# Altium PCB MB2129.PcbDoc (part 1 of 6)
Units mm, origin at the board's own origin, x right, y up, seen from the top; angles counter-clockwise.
Board outline 70 x 133.34 mm, 6 copper layers (Top Layer, Signal Layer 1, Signal Layer 2, Signal Layer 3, Signal Layer 4, Bottom Layer), stack 1.57 mm thick; 377 components, 289 nets, 1482 pads, 1373 vias.
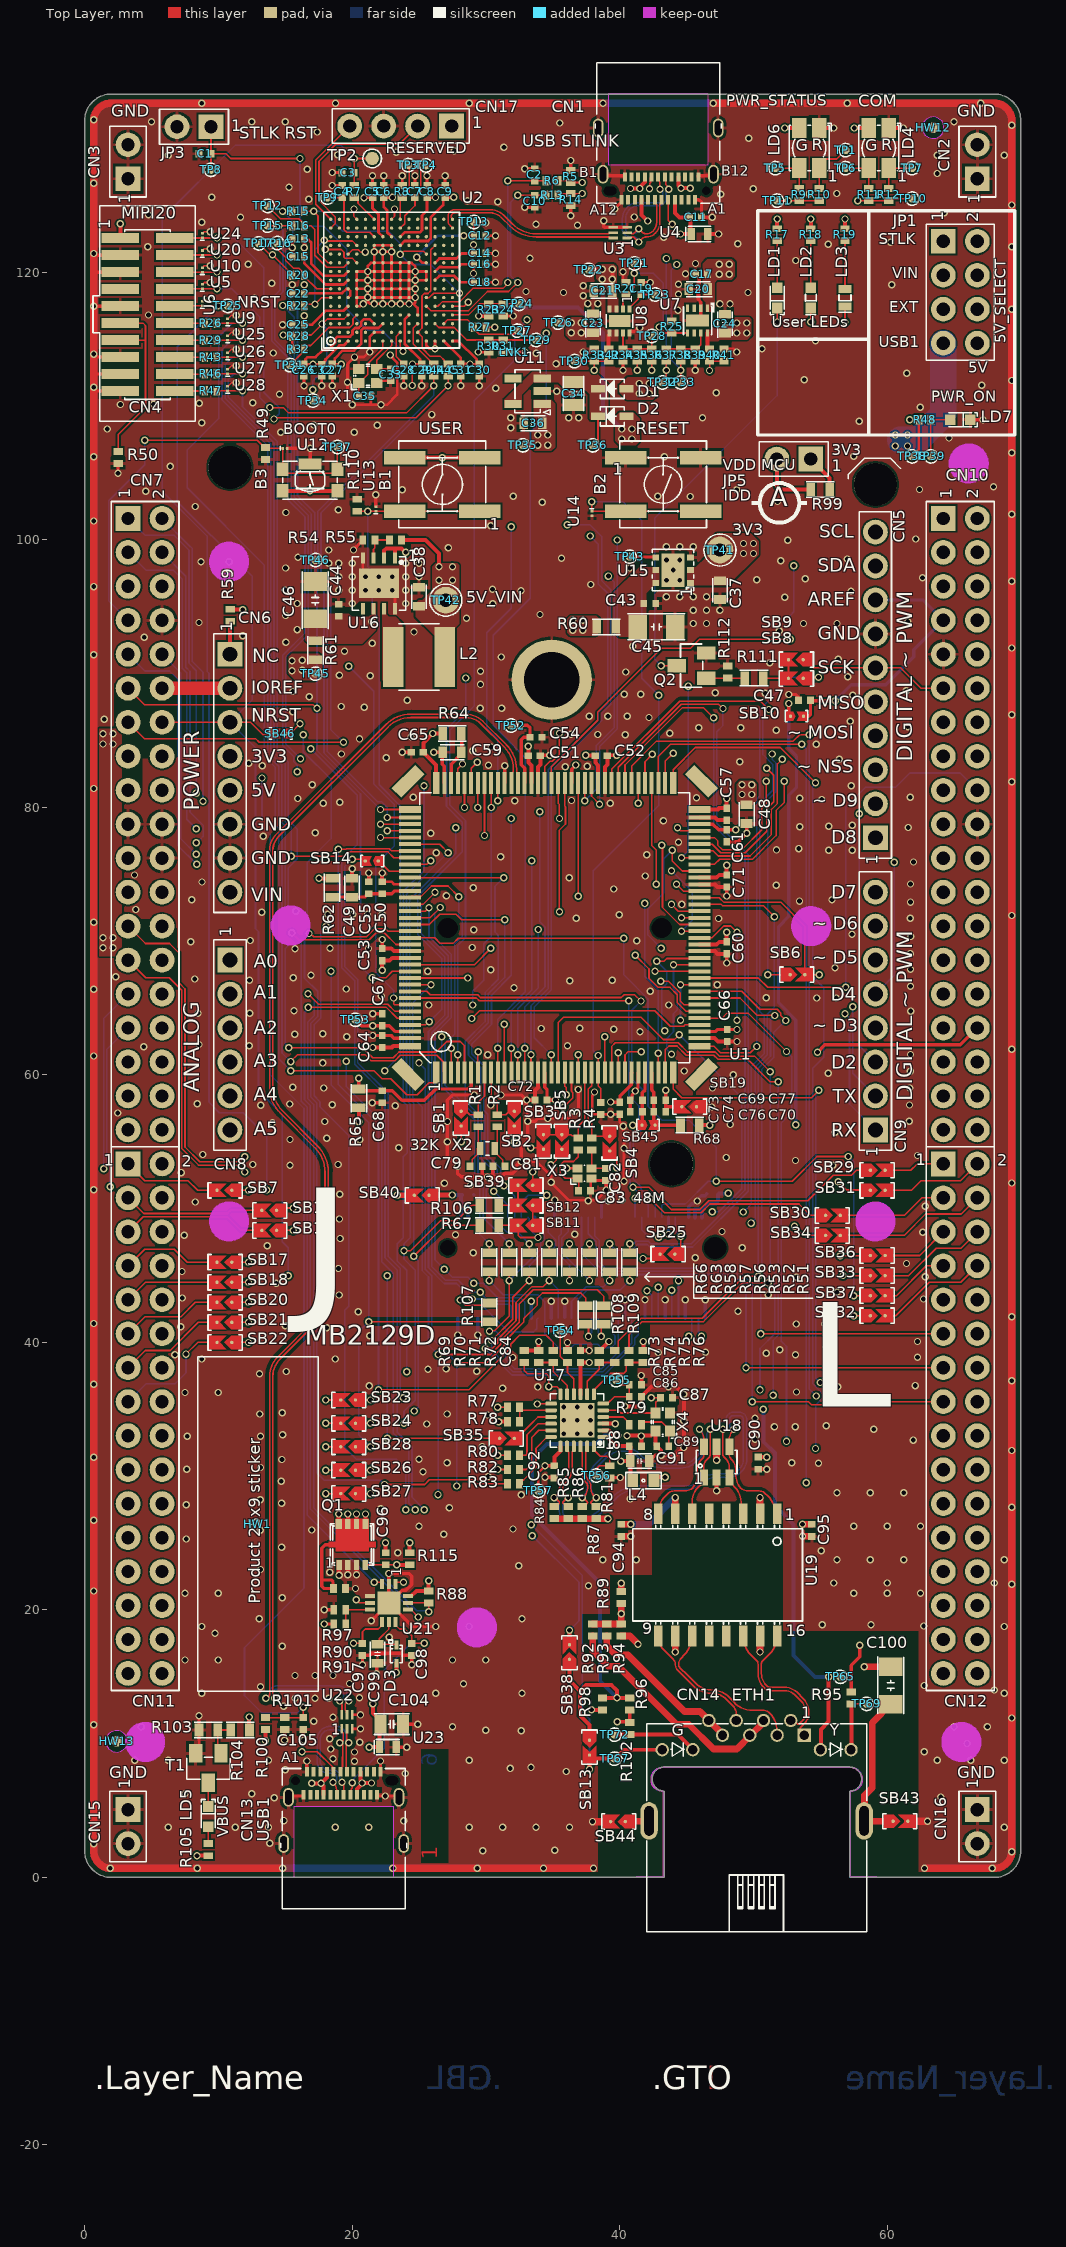
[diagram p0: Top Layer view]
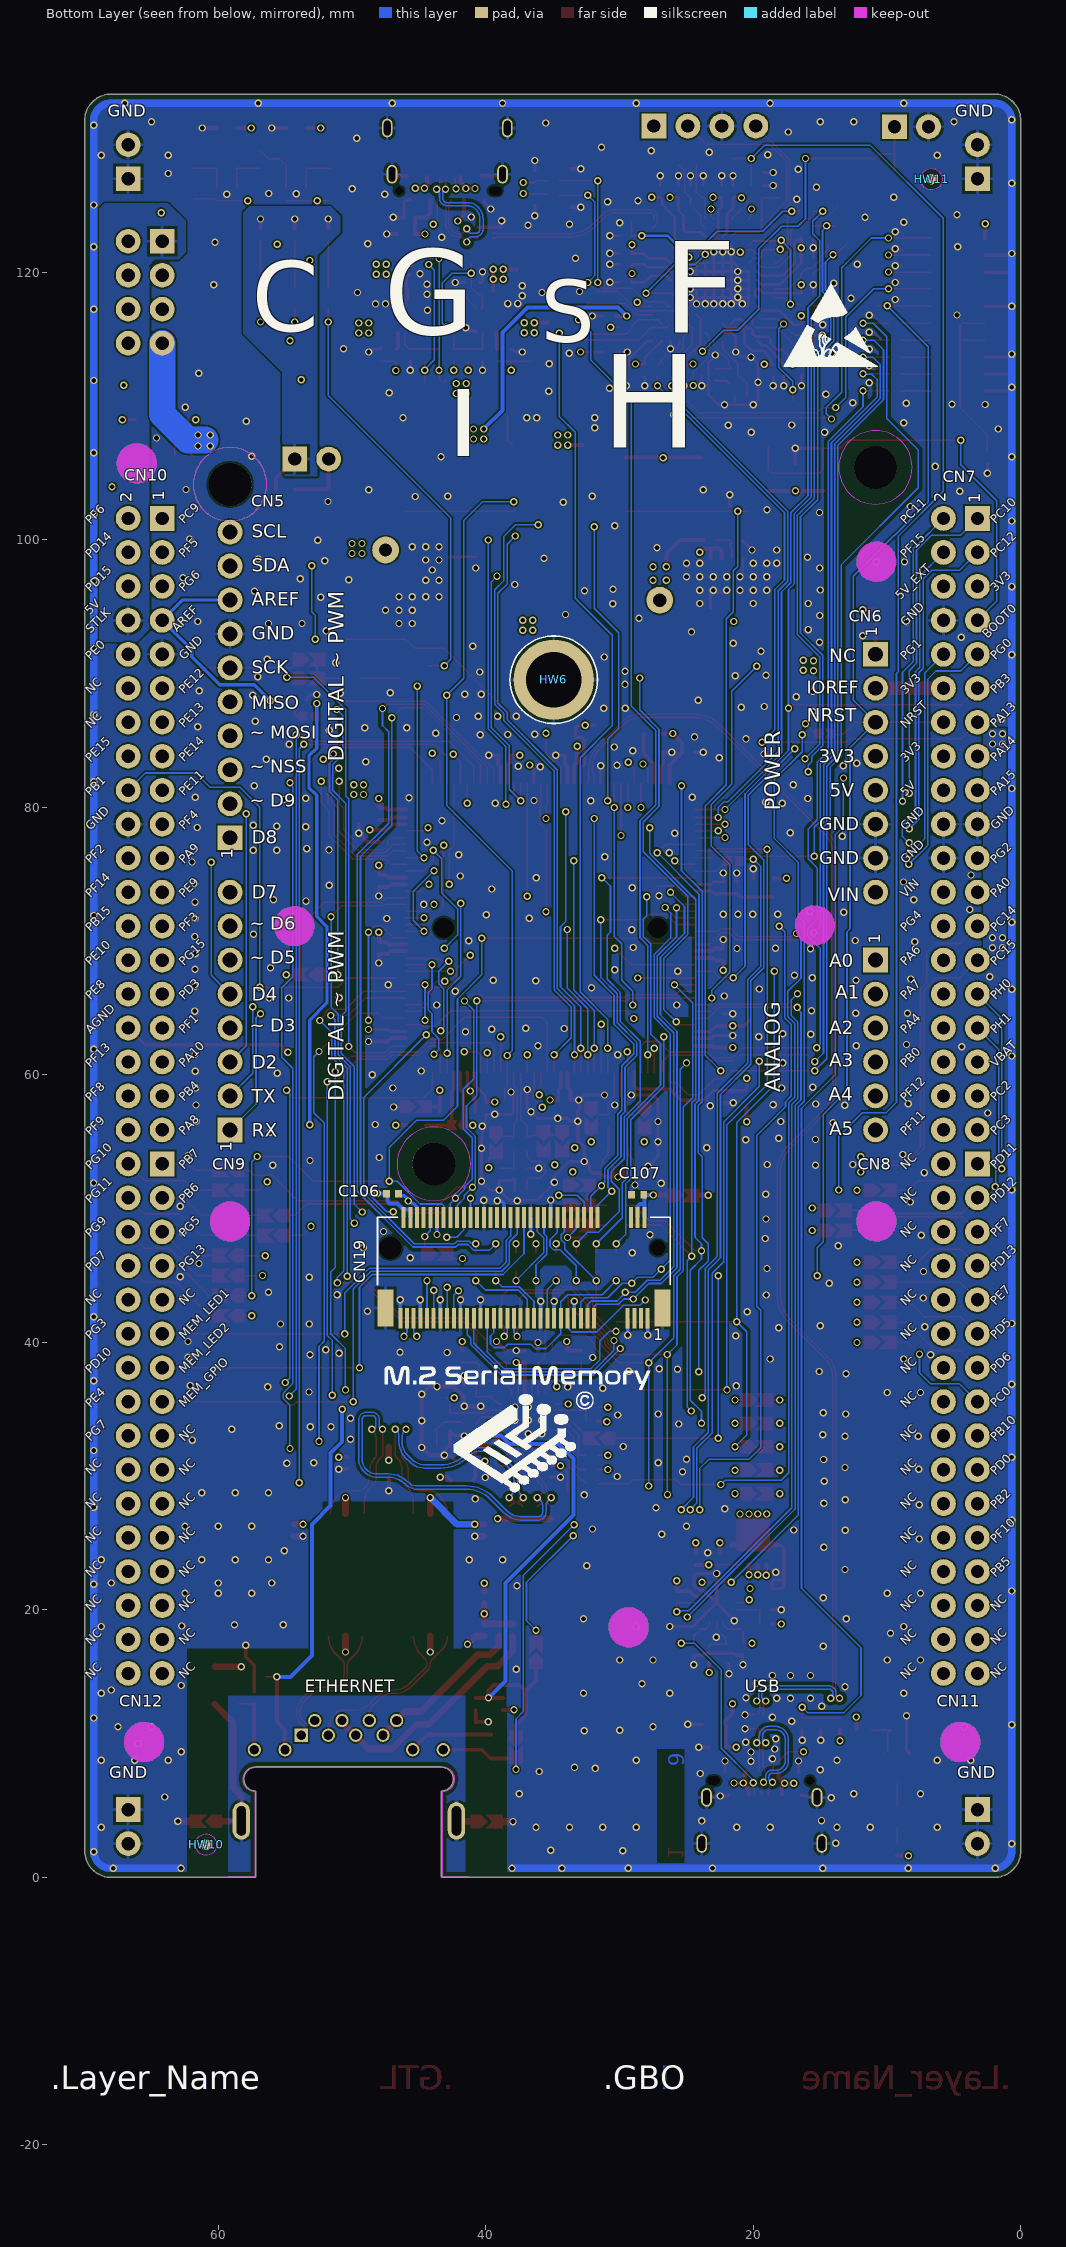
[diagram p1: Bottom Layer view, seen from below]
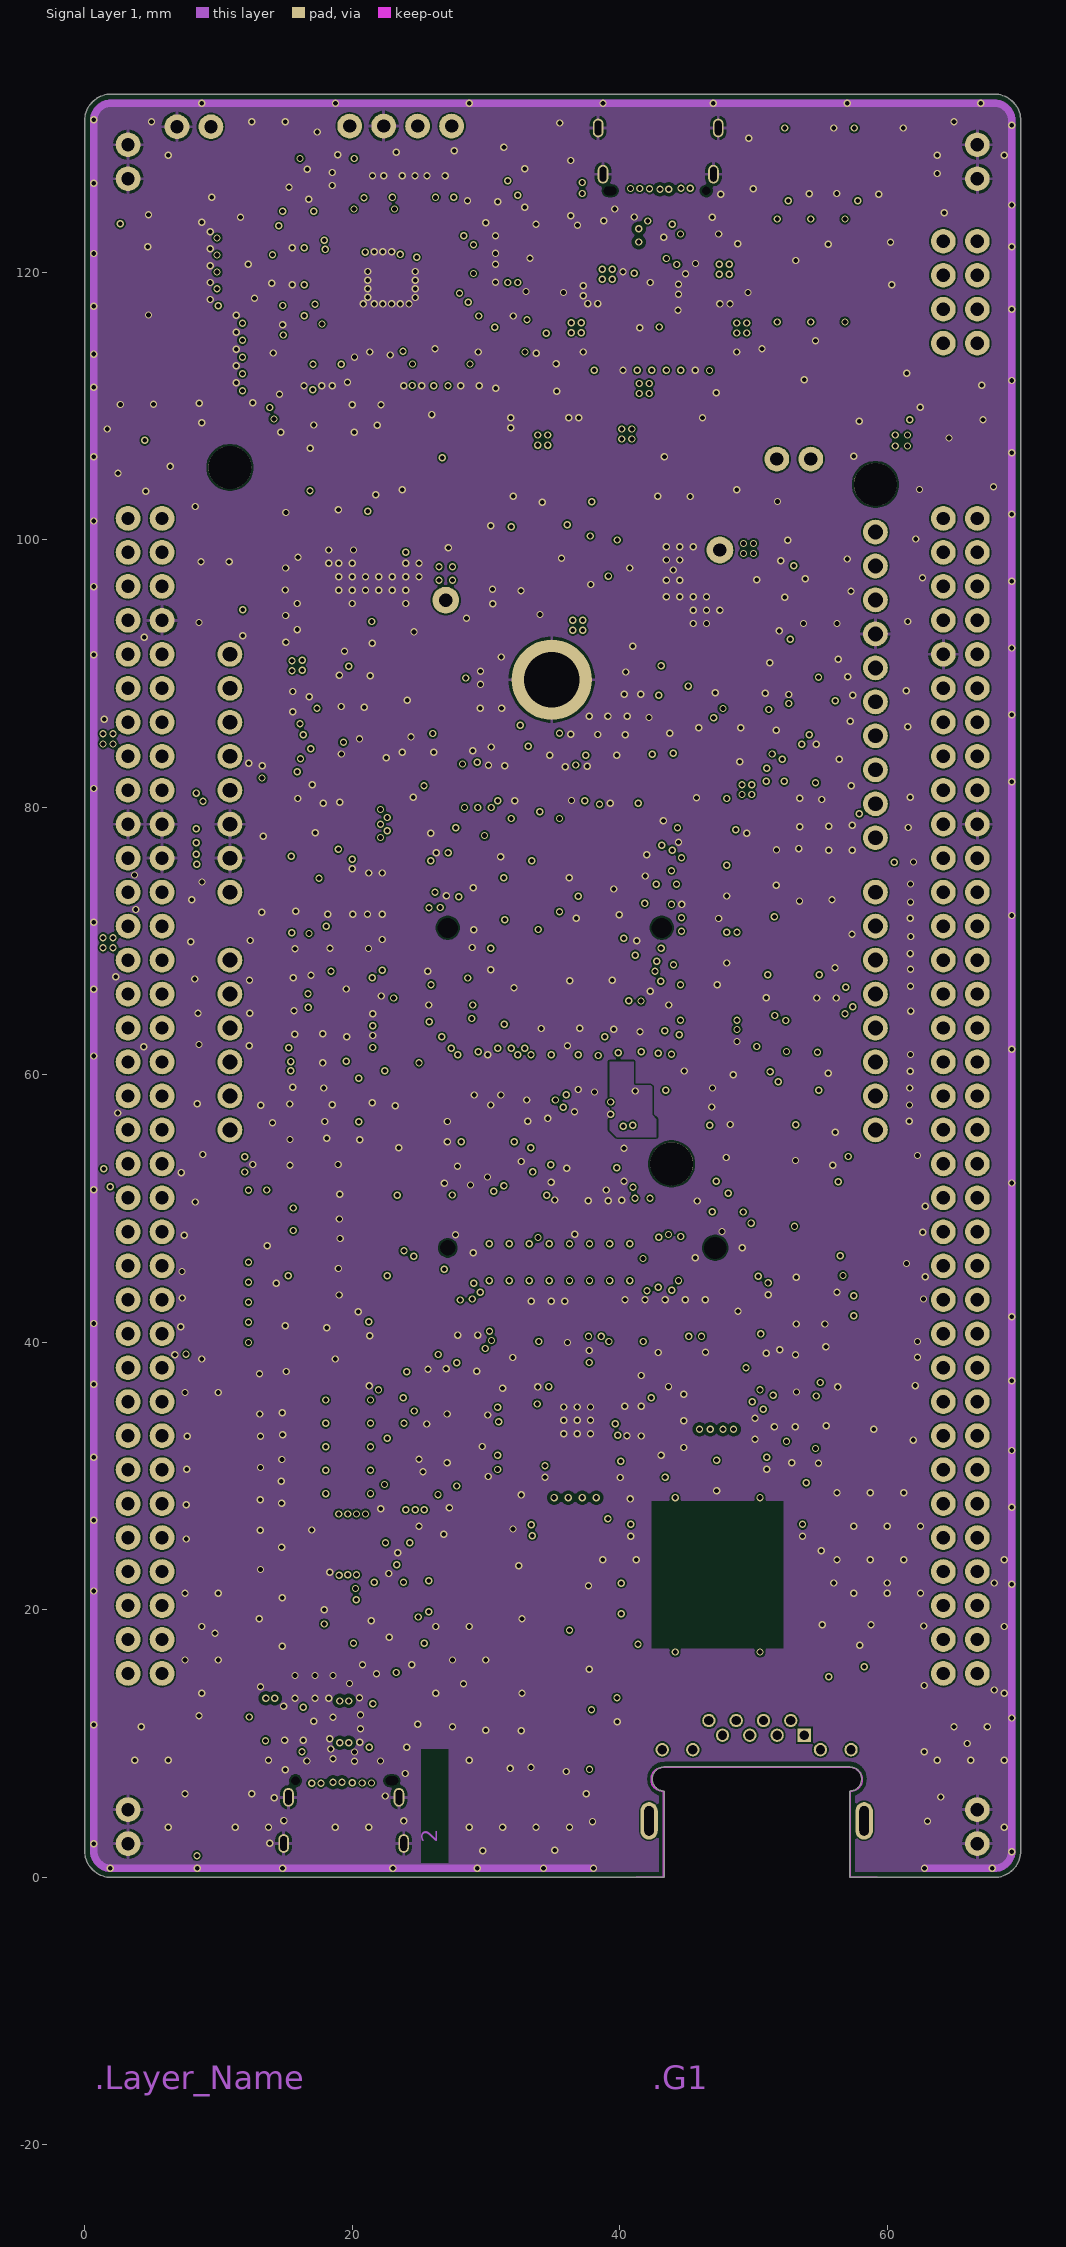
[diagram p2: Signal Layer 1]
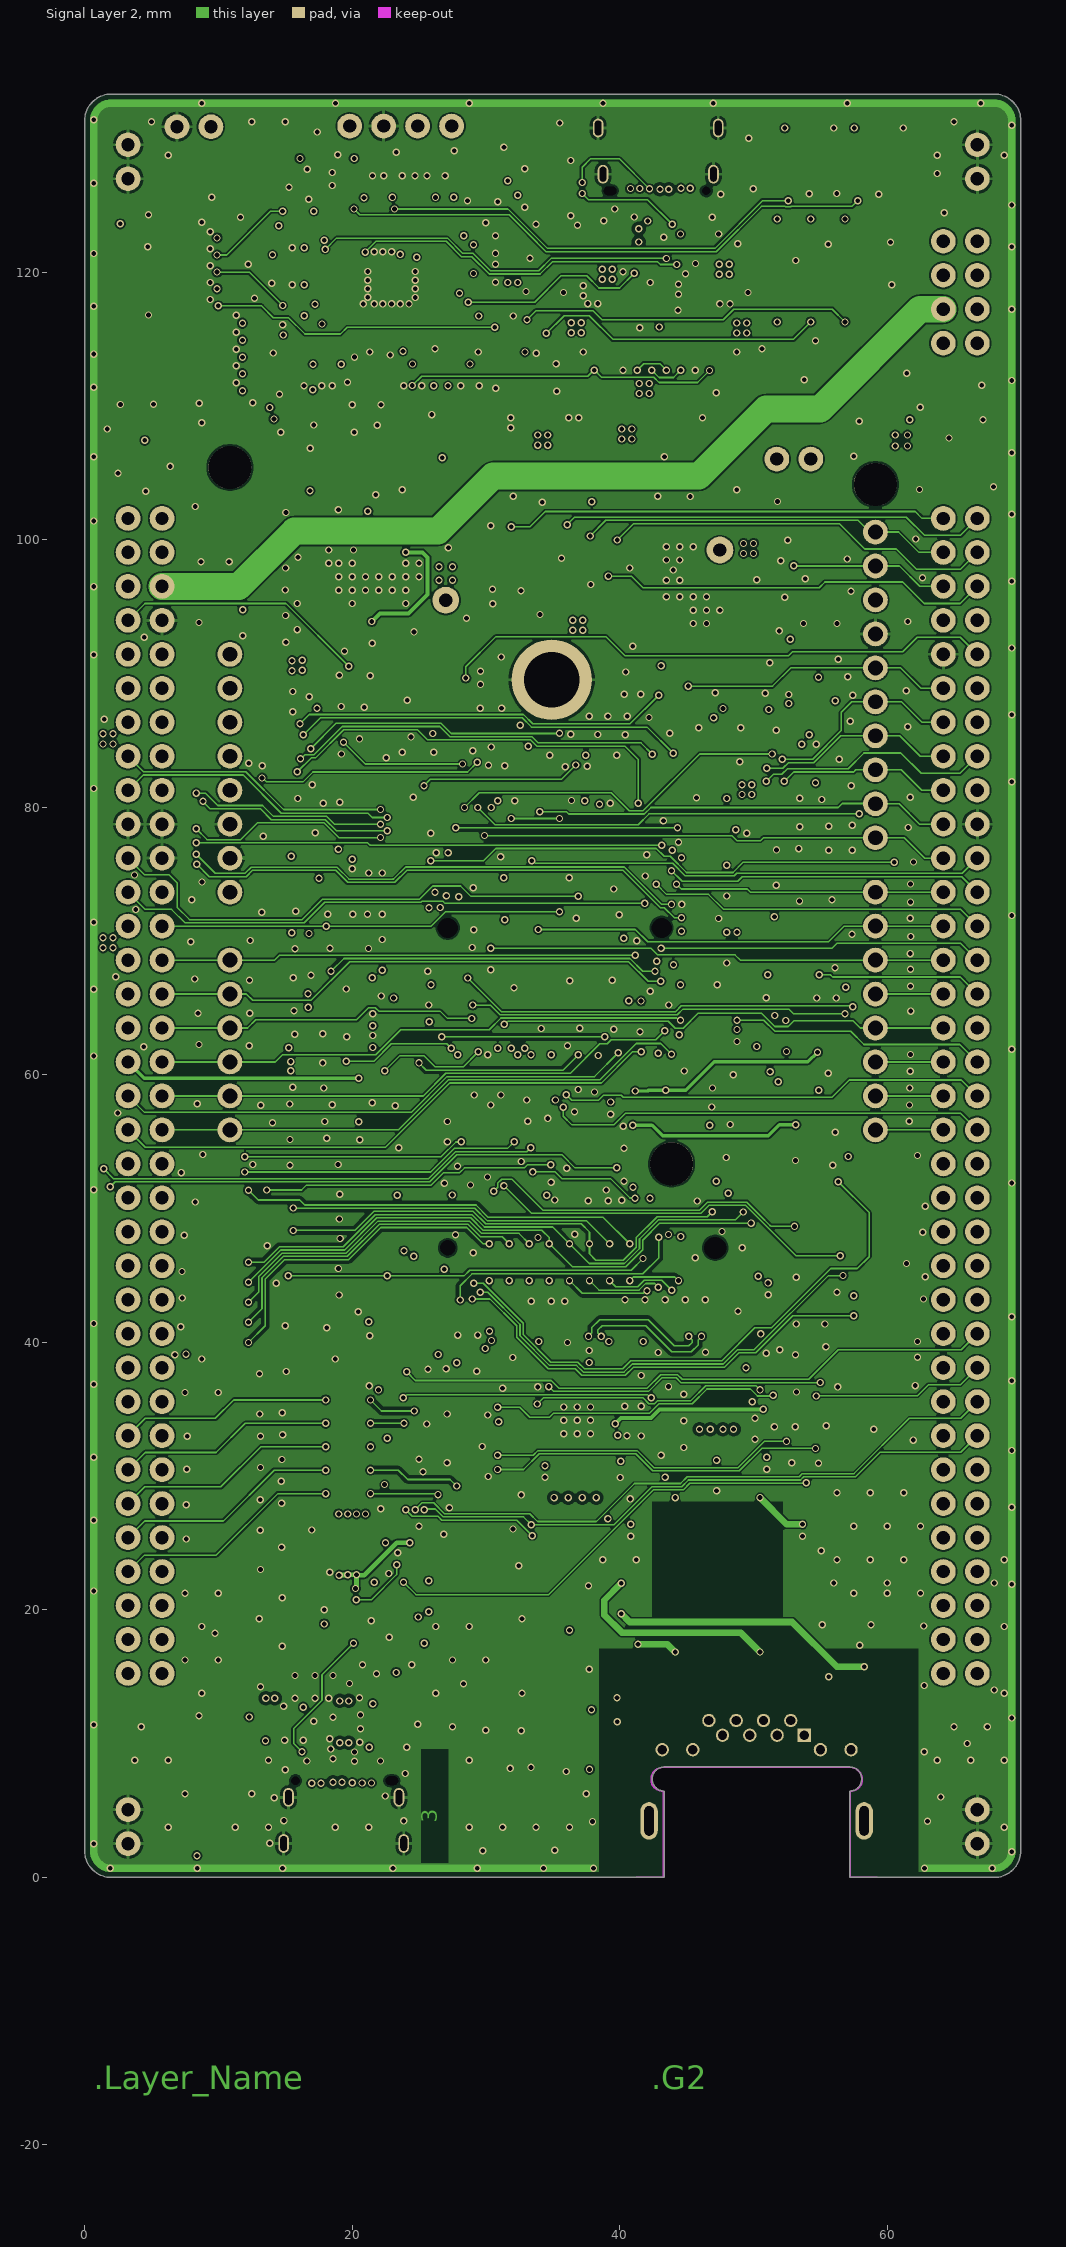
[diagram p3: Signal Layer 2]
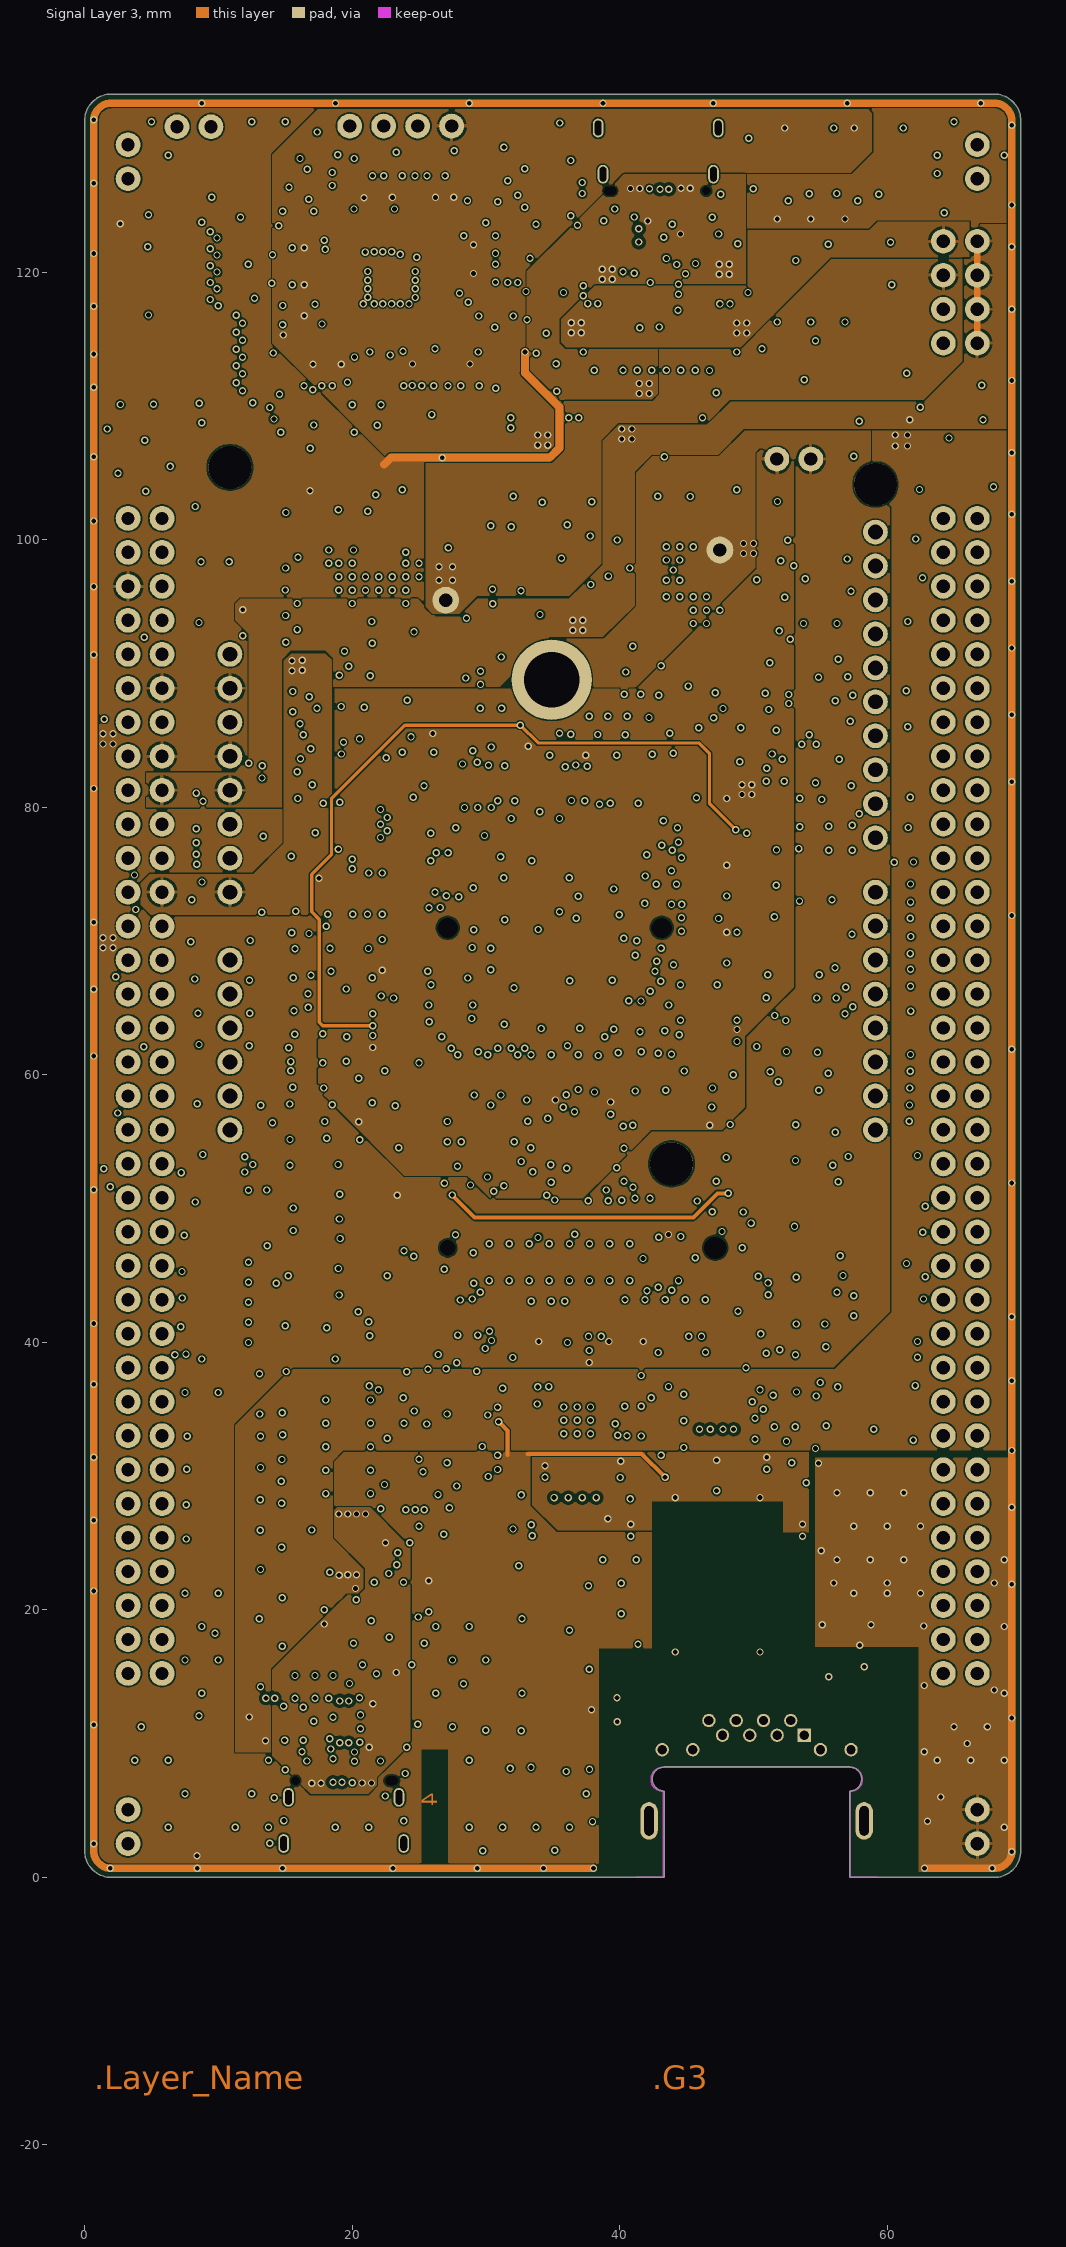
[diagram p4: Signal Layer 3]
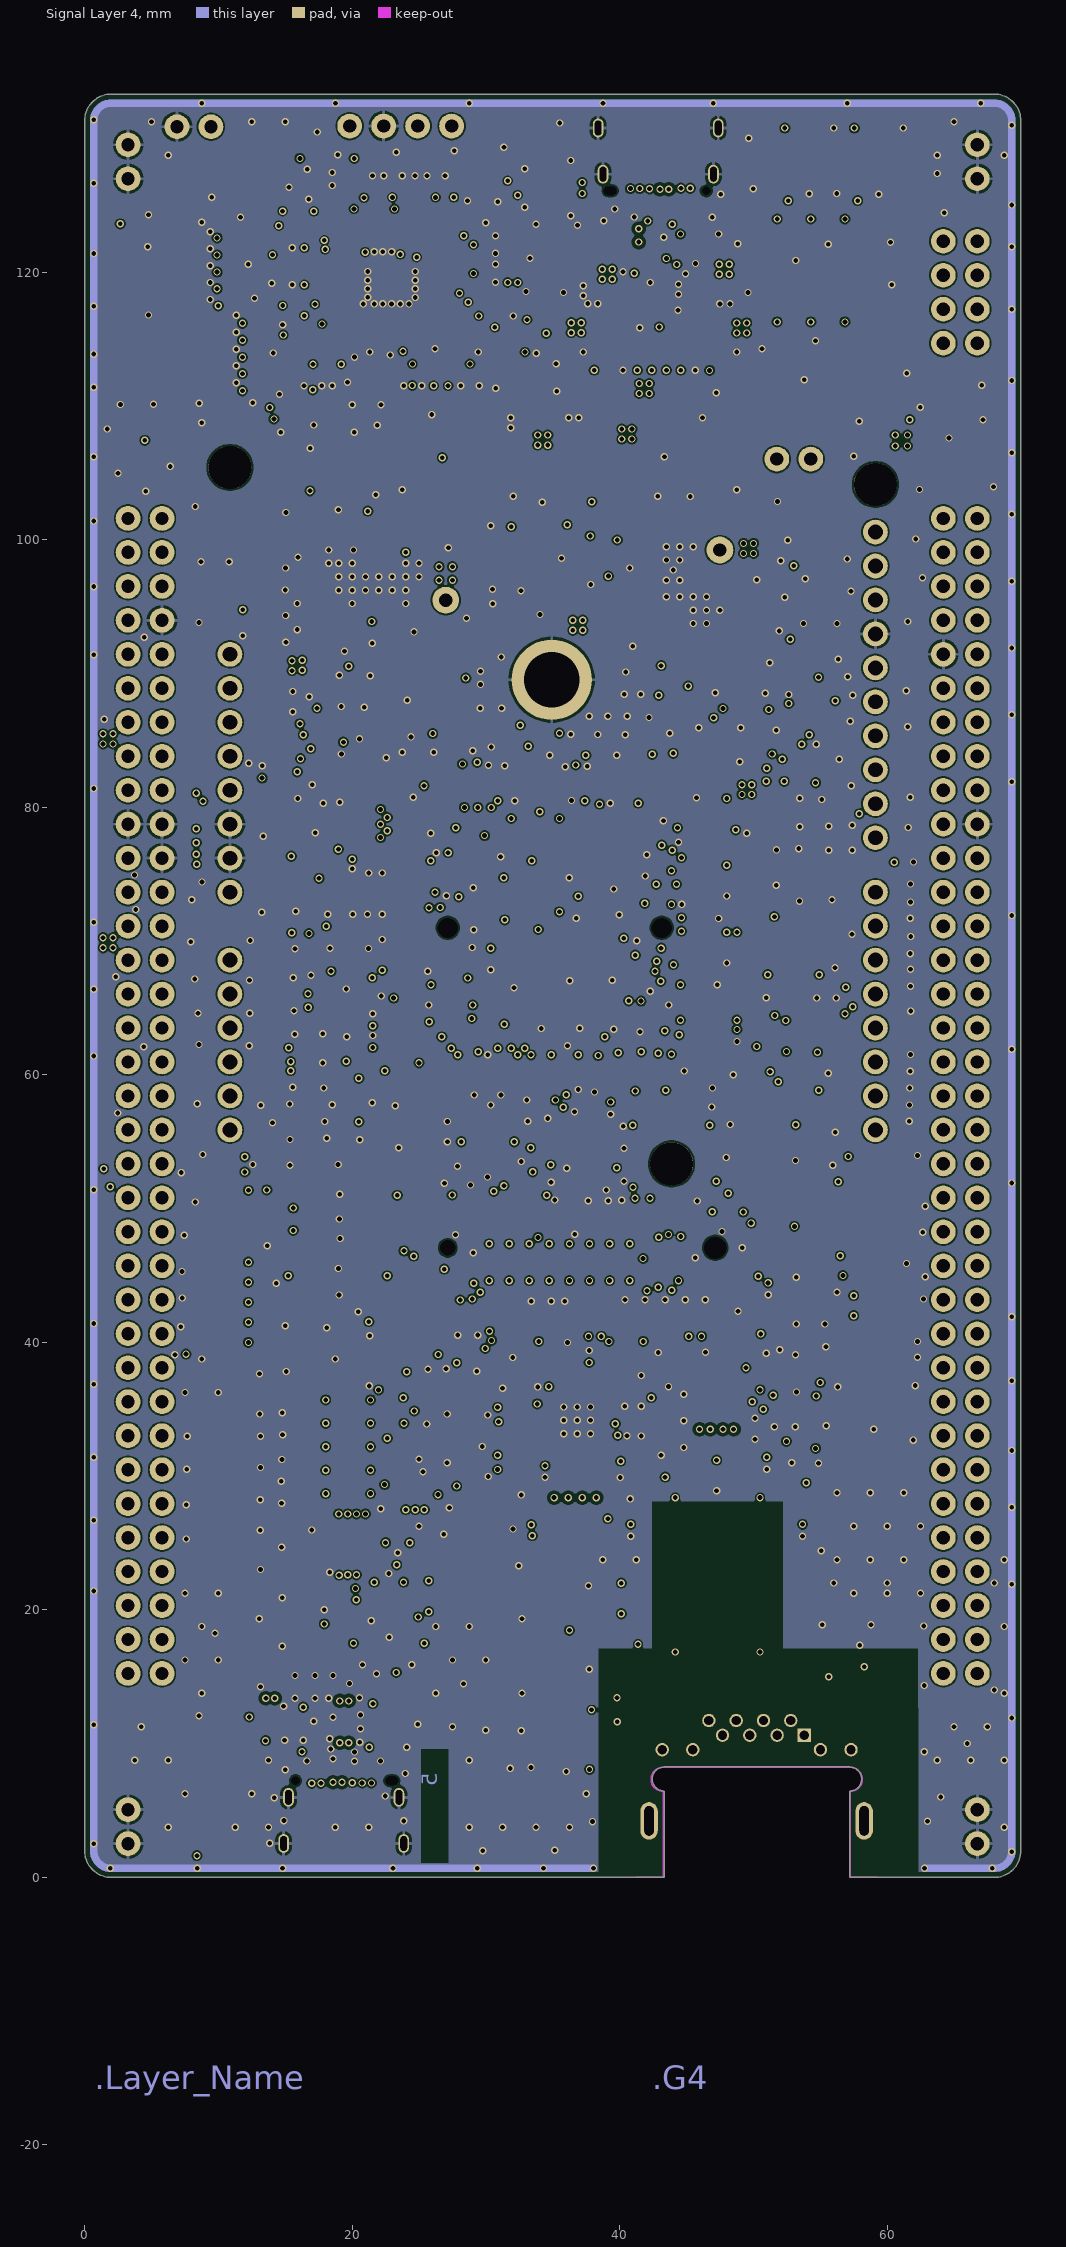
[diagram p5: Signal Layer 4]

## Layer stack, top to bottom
Top Solder: solder mask 0.015, Solder Resist, Dk 3.5
Top Layer: signal copper 0.042
Dielectric 1: core 0.09, FR-4, Dk 4.2
Signal Layer 1: signal copper 0.035
Dielectric 2: prepreg 0.1, FR-4, Dk 4.2
Signal Layer 2: signal copper 0.035
Dielectric 3: core 0.966, FR4, Dk 4.2
Signal Layer 3: signal copper 0.035
Dielectric4: dielectric 0.1, FR-4, Dk 4.2
Signal Layer 4: signal copper 0.035
Dielectric5: core 0.09, FR-4, Dk 4.2
Bottom Layer: signal copper 0.042
Bottom Solder: solder mask 0.015, Solder Resist, Dk 3.5

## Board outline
2,0 40.22,0 43.345,0 43.345,6.458 cw(c43.345,7.358) 42.445,7.358 cw(c43.345,7.358) 43.345,8.258 57.192,8.257 cw(c57.192,7.357) 58.092,7.357 cw(c57.192,7.357) 57.192,6.457 57.192,0 68,0 ccw(c68,2) 70,2 70,131.34 ccw(c68,131.34) 68,133.34 2,133.34 ccw(c2,131.34) 0,131.34 0,2 ccw(c2,2)

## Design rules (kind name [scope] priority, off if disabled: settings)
BoardOutlineClearance [All] p1: gap=0.4 ignorepadtopadclearanceinfootprint=FALSE
Clearance Clearance_KEEPOUT [IsKeepOut] p1: gap=0 ignorepadtopadclearanceinfootprint=FALSE
Clearance Clearance_STLINK [WithinRoom('Room_definition_STLINK')] p2: gap=0.1 ignorepadtopadclearanceinfootprint=FALSE except(0.15: Arc-Hole Track-Hole SMDPad-Hole THPad-Hole Via-Hole Fill-Hole Poly-Hole Region-Hole Text-Hole)
Clearance Clearance_DIFF_PAIR_90 [InNetClass('90 ohms diff')] p3: gap=0.12 ignorepadtopadclearanceinfootprint=FALSE except(0.15: Arc-Hole Track-Hole SMDPad-Hole THPad-Hole Via-Hole Fill-Hole Poly-Hole Region-Hole Text-Hole; 0.25: Arc-Fill Arc-Poly Arc-Region Track-Fill Track-Poly Track-Region Via-Poly)
Clearance Clearance_DIFF_PAIR_100 [InNetClass('100 ohms diff')] p4: gap=0.12 ignorepadtopadclearanceinfootprint=FALSE except(0.15: Arc-Hole Track-Hole SMDPad-Hole THPad-Hole Via-Hole Fill-Hole Poly-Hole Region-Hole Text-Hole; 0.25: Arc-Fill Arc-Poly Arc-Region Track-Fill Track-Poly Track-Region Via-Poly)
Clearance Clearance_SE_50 [InNetClass('50 ohms')] p5: gap=0.12 ignorepadtopadclearanceinfootprint=FALSE except(0.15: Arc-Hole Track-Hole SMDPad-Hole THPad-Hole Via-Hole Fill-Hole Poly-Hole Region-Hole Text-Hole; 0.25: Arc-Fill Arc-Poly Arc-Region Track-Fill Track-Poly Track-Region)
Clearance [All] p6: gap=0.12 ignorepadtopadclearanceinfootprint=FALSE except(0.15: Arc-Hole Track-Hole SMDPad-Hole THPad-Hole Via-Hole Fill-Hole Poly-Hole Region-Hole Text-Hole)
ComponentClearance [HasFootprint('TP_SMD_0-6MM') vs HasFootprint('TP_SMD_0-6MM')] p1: gap=1 collisioncheckmode=3 verticalgap=1 showdistances=FALSE
DiffPairsRouting DiffPairsRouting_DP100 [InDifferentialPairClass('DiffPair_100')] p1: maxlimit=0.5 minlimit=0.127 mostfreqgap=0.35 toplayer_mingap=0.15 toplayer_prefgap=0.15 toplayer_minwidth=0.1 toplayer_maxwidth=0.1 toplayer_prefwidth=0.1 midlayer1_maxgap=0.127 midlayer1_prefgap=0.127 midlayer1_minwidth=0.039 midlayer1_maxwidth=0.039 midlayer1_prefwidth=0.039 midlayer2_mingap=0.35 midlayer2_maxgap=0.35 midlayer2_minwidth=0.1 midlayer2_maxwidth=0.1 midlayer2_prefwidth=0.1 midlayer3_mingap=0.35 midlayer3_maxgap=0.35 midlayer3_minwidth=0.1 midlayer3_maxwidth=0.1 midlayer3_prefwidth=0.1 midlayer4_maxgap=0.127 midlayer4_prefgap=0.127 midlayer4_minwidth=0.039 midlayer4_maxwidth=0.039 midlayer4_prefwidth=0.039 bottomlayer_mingap=0.15 bottomlayer_maxgap=0.15 bottomlayer_prefgap=0.15 bottomlayer_minwidth=0.1 bottomlayer_maxwidth=0.1 bottomlayer_prefwidth=0.1 substack1={2C77A291-11D5-43C1-AB31-C92959FB7931} toplayer_{2c77a291-11d5-43c1-ab31-c92959fb7931}_maxgap=0.127 toplayer_{2c77a291-11d5-43c1-ab31-c92959fb7931}_prefgap=0.127 toplayer_{2c77a291-11d5-43c1-ab31-c92959fb7931}_minwidth=0.095 toplayer_{2c77a291-11d5-43c1-ab31-c92959fb7931}_maxwidth=0.095 toplayer_{2c77a291-11d5-43c1-ab31-c92959fb7931}_prefwidth=0.095 midlayer1_{2c77a291-11d5-43c1-ab31-c92959fb7931}_maxgap=0.127 midlayer1_{2c77a291-11d5-43c1-ab31-c92959fb7931}_prefgap=0.127 midlayer1_{2c77a291-11d5-43c1-ab31-c92959fb7931}_minwidth=0.039 midlayer1_{2c77a291-11d5-43c1-ab31-c92959fb7931}_maxwidth=0.039 midlayer1_{2c77a291-11d5-43c1-ab31-c92959fb7931}_prefwidth=0.039 midlayer2_{2c77a291-11d5-43c1-ab31-c92959fb7931}_maxgap=0.127 midlayer2_{2c77a291-11d5-43c1-ab31-c92959fb7931}_prefgap=0.127 midlayer2_{2c77a291-11d5-43c1-ab31-c92959fb7931}_minwidth=0.054 midlayer2_{2c77a291-11d5-43c1-ab31-c92959fb7931}_maxwidth=0.054 midlayer2_{2c77a291-11d5-43c1-ab31-c92959fb7931}_prefwidth=0.054 midlayer3_{2c77a291-11d5-43c1-ab31-c92959fb7931}_maxgap=0.127 midlayer3_{2c77a291-11d5-43c1-ab31-c92959fb7931}_prefgap=0.127 midlayer3_{2c77a291-11d5-43c1-ab31-c92959fb7931}_minwidth=0.054 midlayer3_{2c77a291-11d5-43c1-ab31-c92959fb7931}_maxwidth=0.054 midlayer3_{2c77a291-11d5-43c1-ab31-c92959fb7931}_prefwidth=0.054 midlayer4_{2c77a291-11d5-43c1-ab31-c92959fb7931}_maxgap=0.127 midlayer4_{2c77a291-11d5-43c1-ab31-c92959fb7931}_prefgap=0.127 midlayer4_{2c77a291-11d5-43c1-ab31-c92959fb7931}_minwidth=0.039 midlayer4_{2c77a291-11d5-43c1-ab31-c92959fb7931}_maxwidth=0.039 midlayer4_{2c77a291-11d5-43c1-ab31-c92959fb7931}_prefwidth=0.039 bottomlayer_{2c77a291-11d5-43c1-ab31-c92959fb7931}_maxgap=0.127 bottomlayer_{2c77a291-11d5-43c1-ab31-c92959fb7931}_prefgap=0.127 bottomlayer_{2c77a291-11d5-43c1-ab31-c92959fb7931}_minwidth=0.095 bottomlayer_{2c77a291-11d5-43c1-ab31-c92959fb7931}_maxwidth=0.095 bottomlayer_{2c77a291-11d5-43c1-ab31-c92959fb7931}_prefwidth=0.095 impedanceprofiledriven=TRUE impedanceprofileid={F6D9F82A-1454-4B43-AB70-057D534168AB} impedanceprofilevalue=100.000000 filterlayerstackid={50C3E69E-F703-4B13-A76B-54CE24676B0F} maxuncoupledlength=12.7
DiffPairsRouting DiffPairsRouting_DP90 [InDifferentialPairClass('DiffPair_90')] p2: maxlimit=0.25 minlimit=0.12 mostfreqgap=0.25 toplayer_maxgap=0.12 toplayer_prefgap=0.12 toplayer_minwidth=0.12 toplayer_maxwidth=0.12 toplayer_prefwidth=0.12 midlayer1_mingap=0.127 midlayer1_maxgap=0.127 midlayer1_prefgap=0.127 midlayer1_minwidth=0.057 midlayer1_maxwidth=0.057 midlayer1_prefwidth=0.057 midlayer2_mingap=0.25 midlayer2_minwidth=0.12 midlayer2_maxwidth=0.12 midlayer2_prefwidth=0.12 midlayer3_mingap=0.25 midlayer3_minwidth=0.12 midlayer3_maxwidth=0.12 midlayer3_prefwidth=0.12 midlayer4_mingap=0.127 midlayer4_maxgap=0.127 midlayer4_prefgap=0.127 midlayer4_minwidth=0.057 midlayer4_maxwidth=0.057 midlayer4_prefwidth=0.057 bottomlayer_maxgap=0.12 bottomlayer_prefgap=0.12 bottomlayer_minwidth=0.12 bottomlayer_maxwidth=0.12 bottomlayer_prefwidth=0.12 substack1={2C77A291-11D5-43C1-AB31-C92959FB7931} toplayer_{2c77a291-11d5-43c1-ab31-c92959fb7931}_mingap=0.127 toplayer_{2c77a291-11d5-43c1-ab31-c92959fb7931}_maxgap=0.127 toplayer_{2c77a291-11d5-43c1-ab31-c92959fb7931}_prefgap=0.127 toplayer_{2c77a291-11d5-43c1-ab31-c92959fb7931}_minwidth=0.125 toplayer_{2c77a291-11d5-43c1-ab31-c92959fb7931}_maxwidth=0.125 toplayer_{2c77a291-11d5-43c1-ab31-c92959fb7931}_prefwidth=0.125 midlayer1_{2c77a291-11d5-43c1-ab31-c92959fb7931}_mingap=0.127 midlayer1_{2c77a291-11d5-43c1-ab31-c92959fb7931}_maxgap=0.127 midlayer1_{2c77a291-11d5-43c1-ab31-c92959fb7931}_prefgap=0.127 midlayer1_{2c77a291-11d5-43c1-ab31-c92959fb7931}_minwidth=0.057 midlayer1_{2c77a291-11d5-43c1-ab31-c92959fb7931}_maxwidth=0.057 midlayer1_{2c77a291-11d5-43c1-ab31-c92959fb7931}_prefwidth=0.057 midlayer2_{2c77a291-11d5-43c1-ab31-c92959fb7931}_mingap=0.127 midlayer2_{2c77a291-11d5-43c1-ab31-c92959fb7931}_maxgap=0.127 midlayer2_{2c77a291-11d5-43c1-ab31-c92959fb7931}_prefgap=0.127 midlayer2_{2c77a291-11d5-43c1-ab31-c92959fb7931}_minwidth=0.08 midlayer2_{2c77a291-11d5-43c1-ab31-c92959fb7931}_maxwidth=0.08 midlayer2_{2c77a291-11d5-43c1-ab31-c92959fb7931}_prefwidth=0.08 midlayer3_{2c77a291-11d5-43c1-ab31-c92959fb7931}_mingap=0.127 midlayer3_{2c77a291-11d5-43c1-ab31-c92959fb7931}_maxgap=0.127 midlayer3_{2c77a291-11d5-43c1-ab31-c92959fb7931}_prefgap=0.127 midlayer3_{2c77a291-11d5-43c1-ab31-c92959fb7931}_minwidth=0.08 midlayer3_{2c77a291-11d5-43c1-ab31-c92959fb7931}_maxwidth=0.08 midlayer3_{2c77a291-11d5-43c1-ab31-c92959fb7931}_prefwidth=0.08 midlayer4_{2c77a291-11d5-43c1-ab31-c92959fb7931}_mingap=0.127 midlayer4_{2c77a291-11d5-43c1-ab31-c92959fb7931}_maxgap=0.127 midlayer4_{2c77a291-11d5-43c1-ab31-c92959fb7931}_prefgap=0.127 midlayer4_{2c77a291-11d5-43c1-ab31-c92959fb7931}_minwidth=0.057 midlayer4_{2c77a291-11d5-43c1-ab31-c92959fb7931}_maxwidth=0.057 midlayer4_{2c77a291-11d5-43c1-ab31-c92959fb7931}_prefwidth=0.057 bottomlayer_{2c77a291-11d5-43c1-ab31-c92959fb7931}_mingap=0.127 bottomlayer_{2c77a291-11d5-43c1-ab31-c92959fb7931}_maxgap=0.127 bottomlayer_{2c77a291-11d5-43c1-ab31-c92959fb7931}_prefgap=0.127 bottomlayer_{2c77a291-11d5-43c1-ab31-c92959fb7931}_minwidth=0.125 bottomlayer_{2c77a291-11d5-43c1-ab31-c92959fb7931}_maxwidth=0.125 bottomlayer_{2c77a291-11d5-43c1-ab31-c92959fb7931}_prefwidth=0.125 impedanceprofiledriven=TRUE impedanceprofileid={401E295D-6922-43B6-BC65-27C2763321C2} impedanceprofilevalue=90.000000 filterlayerstackid={50C3E69E-F703-4B13-A76B-54CE24676B0F} maxuncoupledlength=12.7
HoleSize [All] p1: absolutevalues=TRUE maxlimit=10 minlimit=0.025 maxpercent=80.000 minpercent=20.000
MinimumSolderMaskSliver [All] p1: minsoldermaskwidth=0.013
PlaneConnect [All] p1: planeconnectstyle=Relief reliefexpansion=0.508 reliefentries=4 reliefconductorwidth=0.254 reliefairgap=0.152
PolygonConnect PolygonConnect_via [IsVia] p1: connectstyle=Direct reliefconductorwidth=0.254 reliefentries=4 polygonreliefangle="90 Angle" airgapwidth=0.254
PolygonConnect [All] p2: connectstyle=Relief reliefconductorwidth=0.25 reliefentries=4 polygonreliefangle="90 Angle" airgapwidth=0.2
RoomDefinition Room_definition_STLINK [InComponentClass('Project_Overview')] p1: confinementstyle=ConfineIn formatcopy=TRUE lockcomponents=FALSE outline 13.075,128.325 33.236,128.325 33.236,111.253 13.075,111.253
RoutingVias [All] p1: holewidth=0.35 width=0.55 viastyle="Through Hole" minholewidth=0.35 minwidth=0.55 maxholewidth=0.35 maxwidth=0.55 useviatemplates=TRUE viatemplateguid#1={ADC7A867-5CB9-40BA-B548-23422168BCDB} viatemplatename#1=v55h35m0mx0(1)
SilkToSilkClearance [All] p1: silktosilkclearance=0.013
SilkToSolderMaskClearance [IsPad] p1: minsilkscreentomaskgap=0.013 clearancetoexposedcopper=TRUE
SolderMaskExpansion [All] p1: expansion=0.102 istentingtop=FALSE
SupplyNets "Schematic Supply Nets_17" [InNet('VCAP')] p1: voltage=0.000
SupplyNets "Schematic Supply Nets_22" [InNet('5V_UCPD')] p2: voltage=0.000
SupplyNets "Schematic Supply Nets_20" [InNet('VDDUSB')] p3: voltage=0.000
SupplyNets "Schematic Supply Nets_19" [InNet('VDD_MCU')] p4: voltage=0.000
SupplyNets "Schematic Supply Nets_18" [InNet('5V_STLK')] p5: voltage=0.000
SupplyNets "Schematic Supply Nets_16" [InNet('5V_VIN')] p6: voltage=0.000
SupplyNets "Schematic Supply Nets_15" [InNet('3V3_STLK')] p7: voltage=0.000
SupplyNets "Schematic Supply Nets_14" [InNet('VDDA')] p8: voltage=0.000
SupplyNets "Schematic Supply Nets_13" [InNet('5V_EXT')] p9: voltage=0.000
SupplyNets "Schematic Supply Nets_12" [InNet('VDDIO2')] p10: voltage=0.000
SupplyNets "Schematic Supply Nets_11" [InNet('5V')] p11: voltage=0.000
SupplyNets "Schematic Supply Nets_10" [InNet('GND')] p12: voltage=0.000
SupplyNets "Schematic Supply Nets_9" [InNet('VBUS_STLK')] p13: voltage=0.000
SupplyNets "Schematic Supply Nets_8" [InNet('3V3_Memory')] p14: voltage=0.000
SupplyNets "Schematic Supply Nets_6" [InNet('VREFP')] p15: voltage=0.000
SupplyNets "Schematic Supply Nets_5" [InNet('VBAT')] p16: voltage=0.000
SupplyNets "Schematic Supply Nets_4" [InNet('AGND')] p17: voltage=0.000
SupplyNets "Schematic Supply Nets_3" [InNet('VIN')] p18: voltage=0.000
SupplyNets "Schematic Supply Nets_2" [InNet('VBUSC')] p19: voltage=0.000
SupplyNets "Schematic Supply Nets_1" [InNet('3V3')] p20: voltage=0.000
SupplyNets "Schematic Supply Nets" [InNet('SHGND')] p21: voltage=0.000
Width Width_STLINK [WithinRoom('Room_definition_STLINK')] p1: maxlimit=1 minlimit=0.1 preferedwidth=0.12 substack1={2C77A291-11D5-43C1-AB31-C92959FB7931}
Width Width_SE_50 [InNetClass('50 ohms')] p2: maxlimit=0.12 minlimit=0.056 preferedwidth=0.12 toplayer_minwidth=0.12 midlayer1_maxwidth=0.056 midlayer1_prefwidth=0.056 midlayer2_minwidth=0.12 midlayer3_minwidth=0.12 midlayer4_maxwidth=0.056 midlayer4_prefwidth=0.056 bottomlayer_minwidth=0.12 substack1={2C77A291-11D5-43C1-AB31-C92959FB7931} toplayer_{2c77a291-11d5-43c1-ab31-c92959fb7931}_minwidth=0.145 toplayer_{2c77a291-11d5-43c1-ab31-c92959fb7931}_maxwidth=0.145 toplayer_{2c77a291-11d5-43c1-ab31-c92959fb7931}_prefwidth=0.145 midlayer1_{2c77a291-11d5-43c1-ab31-c92959fb7931}_maxwidth=0.056 midlayer1_{2c77a291-11d5-43c1-ab31-c92959fb7931}_prefwidth=0.056 midlayer2_{2c77a291-11d5-43c1-ab31-c92959fb7931}_minwidth=0.117 midlayer2_{2c77a291-11d5-43c1-ab31-c92959fb7931}_maxwidth=0.117 midlayer2_{2c77a291-11d5-43c1-ab31-c92959fb7931}_prefwidth=0.117 midlayer3_{2c77a291-11d5-43c1-ab31-c92959fb7931}_minwidth=0.117 midlayer3_{2c77a291-11d5-43c1-ab31-c92959fb7931}_maxwidth=0.117 midlayer3_{2c77a291-11d5-43c1-ab31-c92959fb7931}_prefwidth=0.117 midlayer4_{2c77a291-11d5-43c1-ab31-c92959fb7931}_maxwidth=0.056 midlayer4_{2c77a291-11d5-43c1-ab31-c92959fb7931}_prefwidth=0.056 bottomlayer_{2c77a291-11d5-43c1-ab31-c92959fb7931}_minwidth=0.145 bottomlayer_{2c77a291-11d5-43c1-ab31-c92959fb7931}_maxwidth=0.145 bottomlayer_{2c77a291-11d5-43c1-ab31-c92959fb7931}_prefwidth=0.145 impedanceprofiledriven=TRUE impedanceprofileid={40690816-2174-4E93-BC6C-CD66E8DFFA2F} impedanceprofilevalue=50.000000 minimp=50.000000 maximp=50.000000 favimp=50.000000
Width Width_Alim_100mA [InNetClass('Alim_100mA')] p3: maxlimit=1 minlimit=0.2 preferedwidth=0.25 substack1={2C77A291-11D5-43C1-AB31-C92959FB7931}
Width Width_Alim_2A [InNetClass('Alim_2A')] p4: maxlimit=2 minlimit=0.2 preferedwidth=0.3 substack1={2C77A291-11D5-43C1-AB31-C92959FB7931}
Width [All] p5: maxlimit=2 minlimit=0.12 preferedwidth=0.12 substack1={2C77A291-11D5-43C1-AB31-C92959FB7931} toplayer_{2c77a291-11d5-43c1-ab31-c92959fb7931}_minwidth=0.089 toplayer_{2c77a291-11d5-43c1-ab31-c92959fb7931}_maxwidth=1.016 toplayer_{2c77a291-11d5-43c1-ab31-c92959fb7931}_prefwidth=0.254 midlayer1_{2c77a291-11d5-43c1-ab31-c92959fb7931}_minwidth=0.089 midlayer1_{2c77a291-11d5-43c1-ab31-c92959fb7931}_maxwidth=1.016 midlayer1_{2c77a291-11d5-43c1-ab31-c92959fb7931}_prefwidth=0.254 midlayer2_{2c77a291-11d5-43c1-ab31-c92959fb7931}_minwidth=0.089 midlayer2_{2c77a291-11d5-43c1-ab31-c92959fb7931}_maxwidth=1.016 midlayer2_{2c77a291-11d5-43c1-ab31-c92959fb7931}_prefwidth=0.254 midlayer3_{2c77a291-11d5-43c1-ab31-c92959fb7931}_minwidth=0.089 midlayer3_{2c77a291-11d5-43c1-ab31-c92959fb7931}_maxwidth=1.016 midlayer3_{2c77a291-11d5-43c1-ab31-c92959fb7931}_prefwidth=0.254 midlayer4_{2c77a291-11d5-43c1-ab31-c92959fb7931}_minwidth=0.089 midlayer4_{2c77a291-11d5-43c1-ab31-c92959fb7931}_maxwidth=1.016 midlayer4_{2c77a291-11d5-43c1-ab31-c92959fb7931}_prefwidth=0.254 bottomlayer_{2c77a291-11d5-43c1-ab31-c92959fb7931}_minwidth=0.089 bottomlayer_{2c77a291-11d5-43c1-ab31-c92959fb7931}_maxwidth=1.016 bottomlayer_{2c77a291-11d5-43c1-ab31-c92959fb7931}_prefwidth=0.254 minimp=50.000000 maximp=50.000000 favimp=50.000000
23 further rules are at their usual default settings.

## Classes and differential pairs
net class PH[0..15]: PH0 PH1 PH2 PH3 PH4 PH5 PH6 PH7 PH8 PH9 PH10 PH11 PH12 PH13 PH14 PH15
net class PG[0..15]: PG0 PG1 PG2 PG3 PG4 PG5 PG6 PG7 PG8 PG9 PG10 PG11 PG12 PG13 PG14 PG15
net class PF[0..15]: PF0 PF1 PF2 PF3 PF4 PF5 PF6 PF7 PF8 PF9 PF10 PF11 PF12 PF13 PF14 PF15
net class PE[0..15]: PE0 PE1 PE2 PE3 PE4 PE5 PE6 PE7 PE8 PE9 PE10 PE11 PE12 PE13 PE14 PE15
net class PD[0..15]: PD0 PD1 PD2 PD3 PD4 PD5 PD6 PD7 PD8 PD9 PD10 PD11 PD12 PD13 PD14 PD15
net class PC[0..15]: PC0 PC1 PC2 PC3 PC4 PC5 PC6 PC7 PC8 PC9 PC10 PC11 PC12 PC13 PC14 PC15
net class PB[0..15]: PB0 PB1 PB2 PB3 PB4 PB5 PB6 PB7 PB8 PB9 PB10 PB11 PB12 PB13 PB14 PB15
net class PA[0..15]: PA0 PA1 PA2 PA3 PA4 PA5 PA6 PA7 PA8 PA9 PA10 PA11 PA12 PA13 PA14 PA15
differential pair class DiffPair_100: RD RX TD TX
differential pair class DiffPair_90: CON_USB_HS STLK_USB STLK_USB_CN USB_HS
net class "90 ohms diff": CON_USB_HS_N CON_USB_HS_P STLK_USB_CN_N STLK_USB_CN_P STLK_USB_N STLK_USB_P USB_HS_N USB_HS_P
net class ALIM_100mA: VBAT VDDA VDDIO2 VDDUSB VREFP
net class ALIM_2A: 3V3 3V3_Memory 3V3_STLK 5V 5V_EXT 5V_STLK 5V_UCPD 5V_VIN NetC88_2 VBUS_STLK VBUSc VDD_MCU VIN
component class U_Top: HW10 HW11 HW12 HW13
net class "100 ohms diff": RD_N RD_P RX_N RX_P TD_N TD_P TX_N TX_P
net class "50 ohms": NetCN19_22 NetCN19_25 NetCN19_26 NetCN19_27 NetCN19_28 NetCN19_31 NetCN19_32 NetCN19_34 NetCN19_35 NetCN19_37 NetCN19_41 NetCN19_43 NetR106_2 TRACE.CLK TRACE.D0 TRACE.D1 TRACE.D2 TRACE.D3 TRACECLK TRACED0 TRACED1 TRACED2 TRACED3 XSPI1.CLK XSPI1.DQS0 XSPI1.IO0 XSPI1.IO1 XSPI1.IO2 XSPI1.IO3 XSPI1.IO4 XSPI1.IO5 XSPI1.IO6 XSPI1.IO7 XSPI1.NCLK XSPI1.NCS1 XSPI1.NCS2
component class U_M2_SerMem_Connector: C106 C107 CN19 HW6 R51 R52 R53 R56 R57 R58 R63 R66 R67 R106 R107 R108 R109 SB11 SB12 SB25 SB39 SB40
component class U_MCU_IOs: C79 C81 C82 C83 R1 R2 R3 R4 SB1 SB2 SB3 SB4 SB5 TP46 U1 X2 X3
component class U_Ethernet: C84 C85 C86 C87 C88 C89 C90 C91 C92 C94 C95 C100 CN14 L4 R69 R70 R71 R72 R73 R74 R75 R76 R77 R78 R79 R80 R81 R82 R83 R84 R85 R86 R87 R89 R92 R93 R94 R95 R96 R98 R102 SB13 SB14 SB35 SB38 SB43 SB44 TP54 TP55 TP56 TP57 TP65 TP67 TP69 TP72 U17 U18 U19 X4
component class U_External_Debug_Interface: CN4 R26 R29 R43 R46 R47 R50 U5 U6 U9 U10 U20 U24 U25 U26 U27 U28
component class U_STLINK_V3EC: C1 C2 C3 C4 C5 C6 C7 C8 C9 C10 C11 C12 C13 C14 C15 C16 C17 C18 C19 C20 C21 C22 C23 C24 C25 C26 C27 C28 C29 C30 C31 C32 C33 C34 C35 C36 CN1 CN17 D1 D2 JP3 LD4 LD6 LNK1 R5 R6 R7 R8 R9 R10 R11 R12 R13 R14 R15 R16 R20 R21 R22 R23 R24 R25 R27 R28 R30 R31 R32 R33 R34 R35 R36 R37 R38 R39 R40 R41 R42 R44 R45 TP1 TP2 TP3 TP4 TP5 TP6 TP7 TP8 TP9 TP10 TP11 TP12 TP13 TP15 TP16 TP17 TP21 TP22 TP23 TP24 TP25 TP26 TP27 TP28 TP29 TP30 TP31 TP32 TP33 TP34 TP35 TP36 U2 U3 U4 U7 U8 U11 X1
component class U_USB_User_UC2.1: C96 C97 C98 C99 C104 C105 CN13 D3 LD5 Q1 R88 R90 R91 R97 R100 R101 R103 R104 R105 R115 T1 U21 U22 U23
component class U_Power_Sources: C37 C38 C43 C44 C45 C46 CN2 CN3 JP1 L2 LD7 R48 R54 R55 R60 R61 TP38 TP39 TP41 TP42 TP43 U15 U16
component class U_Peripherals: B1 B2 B3 C73 LD1 LD2 LD3 Q2 R17 R18 R19 R49 R110 R111 R112 SB8 SB9 SB46 TP37 U12 U13 U14
component class U_Connectors: C47 CN5 CN6 CN7 CN8 CN9 CN10 CN11 CN12 CN15 CN16 R59 SB6 SB7 SB10 SB15 SB16 SB17 SB18 SB20 SB21 SB22 SB23 SB24 SB26 SB27 SB28 SB29 SB30 SB31 SB32 SB33 SB34 SB36 SB37 TP45
component class U_MCU_Power: C48 C49 C50 C51 C52 C53 C54 C55 C57 C59 C60 C61 C64 C65 C66 C67 C68 C69 C70 C71 C72 C74 C76 C77 JP5 R62 R64 R65 R68 R99 SB19 SB45 TP52 TP53
component class Project_Overview: HW1
differential pair USB_HS: +USB_HS_P -USB_HS_N
differential pair CON_USB_HS: +CON_USB_HS_P -CON_USB_HS_N
differential pair RD: +RD_P -RD_N
differential pair RX: +RX_P -RX_N
differential pair STLK_USB_CN: +STLK_USB_CN_P -STLK_USB_CN_N
differential pair STLK_USB: +STLK_USB_P -STLK_USB_N
differential pair TD: +TD_P -TD_N
differential pair TX: +TX_P -TX_N

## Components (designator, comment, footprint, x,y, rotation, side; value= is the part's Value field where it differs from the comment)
B1 "SW_BLUE_KSC721JLFS" SWI_C&K_KSC721JLFS_BLUE 26.75,104.15 r180 top locked value=KSC721JLFS
B2 "SW_BLACK_KSC321JLFS" SWI_C&K_KSC321JLFS_BLACK 43.25,104.15 r0 top locked value=KSC321JLFS
B3 "SW-PUSH-CMS_KMR2_BLACK" SWI_C&K_Y78B23110FP__ITT_KMR231GLFS 16.85,104.475 r0 top locked value=KMR231GLFS
C1 "Capacitor" C0402 9,128.875 r0 top value=100nF
C2 "Capacitor" C0402 33.65,127.3 r90 top value=10nF
C3 "Capacitor" C0402 19.7,127.475 r0 top value=20pF
C4 "Capacitor" C0402 19.25,126.05 r270 top value=2.2uF
C5 "Capacitor" C0402 21.525,126.05 r90 top value=100nF
C6 "Capacitor" C0402 22.375,126.05 r90 top value=100nF
C7 "Capacitor" C0402 24.7,126.05 r270 top value=2.2uF
C8 "Capacitor" C0402 25.6,126.05 r90 top value=100nF
C9 "Capacitor" C0402 26.95,126.05 r90 top value=100nF
C10 "Capacitor" C0402 33.65,125.325 r270 top value=10nF
C11 "Capacitor" C0402 45.675,124.125 r0 top value=100pF
C12 "Capacitor" C0402 29.55,122.75 r180 top value=2.2uF
C13 "Capacitor" C0402 15.971,122.525 r180 top value=100nF
C14 "Capacitor" C0402 29.55,121.425 r0 top value=100nF
C15 "Capacitor" C0402 15.975,121.175 r180 top value=100nF
C16 "Capacitor" C0402 29.55,120.625 r0 top value=100nF
C17 "Capacitor" C0402 46.125,119.875 r0 top value=1uF
C18 "Capacitor" C0402 29.55,119.275 r0 top value=100nF
C19 "Capacitor" C0402 41.625,118.8 r270 top value=10nF
C20 "Capacitor" C0603 45.875,118.75 r0 top value="100nF / 50V"
C21 "Capacitor" C0603 38.75,118.625 r0 top value="100nF / 50V"
C22 "Capacitor" C0402 15.975,118.4 r180 top value=100nF
C23 "Capacitor" C0603 38,116.2 r270 top value=10uF
C24 "Capacitor" C0603 47.875,116.175 r270 top value=10uF
C25 "Capacitor" C0402 15.975,116.1 r180 top value=100nF
C26 "Capacitor" C0402 16.4,112.7 r270 top value=100nF
C27 "Capacitor" C0402 18.525,112.7 r270 top value=100nF
C28 "Capacitor" C0402 23.85,112.7 r270 top value=10nF
C29 "Capacitor" C0402 25.2,112.7 r270 top value=100nF
C30 "Capacitor" C0402 29.5,112.7 r270 top value=100nF
C31 "Capacitor" C0402 28.125,112.7 r270 top value=100nF
C32 "Capacitor" C0402 17.725,112.695 r270 top value=100nF
C33 "Capacitor" C0402 22.875,112.35 r270 top value=5.6pF
C34 "Capacitor" C0805 36.55,110.95 r90 top value=2.2uF
C35 "Capacitor" C0402 20.95,110.75 r180 top value=5.6pF
C36 "Capacitor" C0603 33.525,108.725 r0 top value=10uF
C37 "Capacitor" C0603_H0P8 47.5,96.25 r90 top value=22uF
C38 "Capacitor" C0603_H0P8 25,95.75 r270 top value=22uF
C43 "Capacitor" C0402 42.25,95.25 r180 top value=100nF
C44 "Capacitor" C0402 19,94.75 r270 top value=100nF
C45 "Capacitor" C1206_H1P6 42.75,93.5 r180 top value=10uF
C46 "Capacitor" C1206_H1P6 17.25,95.5 r270 top value=10uF
C47 "Capacitor" C0402 53.825,88 r180 top value=100nF
C48 "Capacitor" C0603_H0P8 49.5,79.5 r90 top value=4.7uF
C49 "Capacitor" C0603_H0P8 20,74 r270 top value=4.7uF
C50 "Capacitor" C0402 22.25,74 r270 top value=1uF
C51 "Capacitor" C0402_MURATA_GRM155_H0P5 33.625,83.875 r180 top value=100nF
C52 "Capacitor" C0402_MURATA_GRM155_H0P5 38.625,83.875 r180 top value=100nF
C53 "Capacitor" C0402_MURATA_GRM155_H0P5 22.25,69 r270 top value=100nF
C54 "Capacitor" C0402_MURATA_GRM155_H0P5 33.75,85.25 r0 top value=100nF
C55 "Capacitor" C0402 21.25,74 r270 top value=1uF
C57 "Capacitor" C0402_MURATA_GRM155_H0P5 48,79.5 r90 top value=100nF
C59 "Capacitor" C0603_H0P8 27.475,84.125 r0 top value=4.7uF
C60 "Capacitor" C0402_MURATA_GRM155_H0P5 48,69.5 r90 top value=100nF
C61 "Capacitor" C0402_H0P5 48,77.875 r270 top value=2.2uF
C64 "Capacitor" C0402_H0P5 22.25,64.125 r90 top value=2.2uF
C65 "Capacitor" C0402_MURATA_GRM155_H0P5 24.875,84.125 r0 top value=100nF
C66 "Capacitor" C0402_MURATA_GRM155_H0P5 48.05,62.95 r90 top value=100nF
C67 "Capacitor" C0402_MURATA_GRM155_H0P5 22.25,62.5 r270 top value=100nF
C68 "Capacitor" C0402 22.25,58.375 r90 top value=1uF
C69 "Capacitor" C0402 41.25,58.125 r0 top value=100nF
C70 "Capacitor" C0402 43,57.25 r180 top value=100nF
C71 "Capacitor" C0402_MURATA_GRM155_H0P5 48,74.5 r90 top value=100nF
C72 "Capacitor" C0402_MURATA_GRM155_H0P5 34.125,58.125 r0 top value=100nF
C73 "Capacitor" C0402 38.6,57.5 r90 top value=100nF
C74 "Capacitor" C0402_MURATA_GRM155_H0P5 40,57.5 r90 top value=100nF
C76 "Capacitor" C0402 41.25,57.25 r0 top value=1uF
C77 "Capacitor" C0402 43,58.125 r180 top value=1uF
C79 "Capacitor" C0402 29.275,53.18 r180 top value=6.8pF
C81 "Capacitor" C0402 30.975,53.18 r0 top value=6.8pF
C82 "Capacitor" C0402 38.956,52.564 r270 top value=3.3pF
C83 "Capacitor" C0402 37.381,51.339 r0 top value=3.3pF
C84 "Capacitor" C0402 37.075,38.95 r270 top value=100nF
C85 "Capacitor" C0402 41.175,36.825 r180 top value=1uF
C86 "Capacitor" C0402 41.175,35.95 r180 top value=470pF
C87 "Capacitor" C0402 43.5,35.875 r180 top value=5.6pF
C88 "Capacitor" C0402 41.175,32.25 r180 top value=100nF
C89 "Capacitor" C0402 43.225,32.25 r0 top value=5.6pF
C90 "Capacitor" C0402 50.35,30.975 r90 top value=100nF
C91 "Capacitor" C0603 41.5,31.125 r180 top value=10uF
C92 "Capacitor" C0402 35.125,30.325 r90 top value=100nF
C94 "Capacitor" C0402 40.125,25.95 r90 top value=100nF
C95 "Capacitor" C0402 54.375,25.95 r90 top value=100nF
C96 "Capacitor" C0402 22.5,23.825 r90 top value=10nF
C97 "Capacitor" C0402 20.775,17.05 r270 top value=330pF
C98 "Capacitor" C0402 24.45,17.05 r270 top value=330pF
C99 "Capacitor" C0603 21.9,16.725 r270 top value=100nF
C100 "Capacitor" C1206_H1P6 60.275,14.35 r90 top value=1nF
C104 "Capacitor" C0805 22.97,11.46 r0 top value=2.2uF
C105 "Capacitor" C0402 16.35,11.5 r90 top value=10pF
C106 "Capacitor" C0402 46.975,51.125 r0 bottom value=1uF
C107 "Capacitor" C0402 28.65,51.025 r180 bottom value=1uF
CN1 "USB_TYPE_C_Receptacle" CON_USB-TYPEC_AMPHENOL_12401826E412A 42.885,126.1 r180 top locked value=USB_C_12401826E412A
CN2 "Jumper_Header 2x1" CON_SAMTEC_TSW-102-09-X-S 66.746,128.28 r90 top locked value="Header 2x1"
CN3 "Jumper_Header 2x1" CON_SAMTEC_TSW-102-09-X-S 3.246,128.28 r90 top locked value="Header 2x1"
CN4 "Header 10x2" CON_SAMTEC_FTSH-110-01-L-DV 4.7,116.85 r270 top locked
CN5 "Socket 10x1" CON_SAMTEC_SSW-110-01-X-S 59.126,89.164 r90 top locked
CN6 "Socket 8x1" CON_SAMTEC_SSW-108-01-X-S 10.866,82.56 r270 top locked
CN7 "Header 19x2" CON_SAMTEC_TSW-119-09-X-D 4.516,78.75 r270 top locked
CN8 "Socket 6x1" CON_SAMTEC_SSW-106-01-X-S 10.866,62.24 r270 top locked
CN9 "Socket 8x1" CON_SAMTEC_SSW-108-01-X-S 59.126,64.78 r90 top locked
CN10 "Header 19x2" CON_SAMTEC_TSW-119-09-X-D 65.476,78.75 r270 top locked
CN11 "Header 16x2" CON_SAMTEC_TSW-116-07-G-D 4.516,34.3 r270 top locked
CN12 "Header 16x2" CON_SAMTEC_TSW-116-07-G-D 65.476,34.3 r270 top locked
CN13 "USB_TYPE_C_Receptacle" CON_USB-TYPEC_AMPHENOL_12401826E412A 19.37,7.235 r0 top locked value=USB_C_12401826E412A
CN14 "RJ45_KRJ-CB4.2GYZNL" CON_RJ45_DGKYD_KRJ-CB4.2GYZNL 50.245,0.03 r0 top locked
CN15 "Jumper_Header 2x1" CON_SAMTEC_TSW-102-09-X-S 3.246,3.8 r270 top locked value="Header 2x1"
CN16 "Jumper_Header 2x1" CON_SAMTEC_TSW-102-09-X-S 66.746,3.8 r270 top locked value="Header 2x1"
CN17 "Header 4x1" CON_SAMTEC_TSW-104-07-G-S 23.625,130.95 r180 top locked
CN19 "M2-Generic_Socket-KeyA" CON_AMPHENOL_MDT-420-A-03001 37.15,45.575 r0 bottom locked value="Socket 67pins"
D1 "SCHOTTKY_1A_2K" DIO_SOD323_1A_2K 39.45,111.3 r180 top value=BAT20JFILM
D2 "SCHOTTKY_1A_2K" DIO_SOD323_1A_2K 39.45,109.25 r180 top value=BAT20JFILM
D3 "SCHOTTKY_1A_2K" DIO_SOD523_1A_2K 23.3,16.7 r90 top value=BAT54KFILM
HW1 "STICKER_PRODUCT" STICKER_PRODUCT_25X9 12.954,26.416 r90 top locked value="Sticker product"
HW6 "M2_POSITION_HOLE" MISC_REGO_S001_00001_A42_R 34.925,89.55 r0 bottom locked value=S001-00001-A42-R
HW10 "FiducialPad" MIRE_PLACE_SMD_0P8MM 60.925,2.45 r270 bottom value="Fiducial Pad"
HW11 "FiducialPad" MIRE_PLACE_SMD_0P8MM 6.675,126.975 r270 bottom value="Fiducial Pad"
HW12 "FiducialPad" MIRE_PLACE_SMD_0P8MM 63.45,130.825 r90 top value="Fiducial Pad"
HW13 "FiducialPad" MIRE_PLACE_SMD_0P8MM 2.4,10.175 r270 top value="Fiducial Pad"
JP1 "Jumper_Header 4x2 Fitted 1-2" CON_SAMTEC_TSW-104-07-X-D 65.475,118.525 r270 top locked value="Header 4x2"
JP3 "Jumper_Header 2x1" CON_SAMTEC_TSW-102-07-G-S 8.175,130.9 r180 top locked value="Header 2x1"
JP5 "IDD" CON_SAMTEC_TSW-102-07-G-S 53.025,106.05 r180 top locked
L2 "Inductor" IND_5040_WURTH_74404054033 25,91.25 r180 top value=3.3uH
L4 "BEAD" L0603 41.775,29.675 r180 top value="600R @100MHz"
LD1 "LED_green" LED_0603_OSRAM_LG-Q396-PS-35_GREEN_1A2K_H0P4 51.775,118.1 r270 top locked value=Green
LD2 "LED_red" LED_0603_RED 54.3,118.1 r270 top locked value=Red
LD3 "LED_blue" LED_0603_SMD-B_BLUE_H0P4 56.85,118.1 r270 top locked value=Blue
LD4 "LED_BICOLOR" LED_BI-GR_WE-150141SV73110 59.375,129.3 r180 top value=Red/Green
LD5 "LED_green" LED_0603_OSRAM_LG-Q396-PS-35_GREEN_1A2K_H0P4 9.25,4.55 r90 top locked value=Green
LD6 "LED_BICOLOR" LED_BI-GR_WE-150141SV73110 54.175,129.3 r180 top value=Green/Red
LD7 "LED_green" LED_0603_OSRAM_LG-Q396-PS-35_GREEN_1A2K_H0P4 65.475,109 r0 top locked value=Green
LNK1 "link_200" LINK200 32.125,114.05 r90 top
Q1 "STL11N3LLH6" MOS_POWERFLAT_3P3X3P3_P065 20,24.9 r0 top
Q2 "9013-SOT23" NPN_SOT23 45.377,90.6 r90 top value="NPN SOT23"
R1 "Resistor" R0402 29.425,56.58 r90 top locked value=0R
R2 "Resistor" R0402 30.85,56.58 r90 top locked value=0R
R3 "Resistor" R0402 36.906,54.839 r270 top locked value=0R
R4 "Resistor" R0402 37.906,54.839 r270 top locked value=0R
R5 "Resistor" R0402 36.35,127.175 r90 top value=5K1
R6 "Resistor" R0402 34.95,126.85 r0 top value=100K
R7 "Resistor" R0402 20.15,126.05 r90 top value=100R
R8 "Resistor" R0402 23.75,126.05 r90 top value=3K
R9 "Resistor" R0402 53.425,125.825 r270 top value=330R
R10 "Resistor" R0402 54.925,125.825 r270 top value=1K
R11 "Resistor" R0402 58.625,125.825 r90 top value=330R
R12 "Resistor" R0402 60.125,125.825 r270 top value=1K
R13 "Resistor" R0402 34.95,125.775 r0 top value=100K
R14 "Resistor" R0402 36.35,125.45 r270 top value=5K1
R15 "Resistor" R0402 15.971,124.575 r180 top value=33R
R16 "Resistor" R0402 15.971,123.5 r180 top value=0R
R17 "Resistor" R0402 51.775,122.825 r90 top value=510R
R18 "Resistor" R0402 54.3,122.825 r90 top value=510R
R19 "Resistor" R0402 56.85,122.825 r90 top value=330R
R20 "Resistor" R0402 15.975,119.8 r180 top value=33R
R21 "Resistor" R0402 40.475,118.8 r270 top value=100K
R22 "Resistor" R0402 15.975,117.525 r180 top value=0R
R23 "Resistor" R0402 30.225,117.2 r270 top value=5K1
R24 "Resistor" R0402 31.3,117.2 r270 top value=10K
R25 "Resistor" R0402 43.9,115.925 r270 top value=100K
R26 "Resistor" R0402 9.425,116.2 r0 top value=0R
R27 "Resistor" R0402 29.55,115.9 r0 top value=0R
R28 "Resistor" R0402 15.975,115.225 r180 top value=10K
R29 "Resistor" R0402 9.425,114.925 r0 top value=0R
R30 "Resistor" R0402 30.225,114.5 r270 top value=10K
R31 "Resistor" R0402 31.3,114.5 r270 top value=10K
R32 "Resistor" R0402 15.975,114.25 r180 top value=10K
R33 "Resistor" R0402 38.1,113.825 r270 top value=3K9
R34 "Resistor" R0402 40.25,113.825 r270 top value=3K9
R35 "Resistor" R0402 41.325,113.825 r270 top value=1K8
R36 "Resistor" R0402 42.4,113.825 r270 top value=1K3
R37 "Resistor" R0402 43.5,113.825 r270 top value=680K
R38 "Resistor" R0402 44.575,113.825 r270 top value=470K
R39 "Resistor" R0402 45.65,113.825 r270 top value=1M3
R40 "Resistor" R0402 46.725,113.825 r270 top value=3K
R41 "Resistor" R0402 47.8,113.825 r270 top value=3K9
R42 "Resistor" R0402 39.175,113.825 r270 top value=3K
R43 "Resistor" R0402 9.425,113.65 r0 top value=0R
R44 "Resistor" R0402 26.1,112.7 r270 top value=33R
R45 "Resistor" R0402 27.175,112.7 r270 top value=33R
R46 "Resistor" R0402 9.425,112.425 r0 top value=0R
R47 "Resistor" R0402 9.425,111.15 r0 top value=0R
R48 "Resistor" R0402 62.825,109 r180 top value=1K2
R49 "Resistor" R0402 13.525,106.475 r90 top value=10K
R50 "Resistor" R0402 2.5,106.175 r90 top value=0R
R51 "Resistor" R0603 40.75,46 r270 top value=0R
R52 "Resistor" R0603 39.25,46 r270 top value=0R
R53 "Resistor" R0603 37.75,46 r270 top value=0R
R54 "Resistor" R0402 21.25,100 r0 top value=15K
R55 "Resistor" R0402 23.25,100 r0 top value=80K6
R56 "Resistor" R0603 36.25,46 r270 top value=0R
R57 "Resistor" R0603 34.75,46 r270 top value=0R
R58 "Resistor" R0603 33.25,46 r270 top value=0R
R59 "Resistor" R0402 10.875,94.375 r90 top value=1K
R60 "Resistor" R0603 39,93.5 r0 top value=0R
R61 "Resistor" R0603 17.25,91.75 r90 top value=0R
R62 "Resistor" R0603 18.5,74 r270 top value=0R
R63 "Resistor" R0603 31.75,46 r270 top value=0R
R64 "Resistor" R0603 27.475,85.525 r0 top value=0R
R65 "Resistor" R0603 20.5,58.25 r90 top value=0R
R66 "Resistor" R0603 30.25,46 r270 top value=0R
R67 "Resistor" R0603 30.25,48.75 r0 top value=0R
R68 "Resistor" R0603 45.25,56.25 r180 top value=0R
R69 "Resistor" R0402 32.875,38.95 r90 top value=1K5
R70 "Resistor" R0402 33.95,38.95 r90 top value=10K
R71 "Resistor" R0402 35.025,38.95 r270 top value=33R
R72 "Resistor" R0402 36.1,38.95 r90 top value=10K
R73 "Resistor" R0402 38.475,38.95 r90 top value=10K
R74 "Resistor" R0402 39.625,38.95 r270 top value=33R
R75 "Resistor" R0402 40.7,38.95 r270 top value=33R
R76 "Resistor" R0402 41.775,38.95 r90 top value=10K
R77 "Resistor" R0402 32.075,35.15 r0 top value=33R
R78 "Resistor" R0402 32.075,34.075 r180 top value=10K
R79 "Resistor" R0402 41.175,33.85 r180 top value=0R
R80 "Resistor" R0402 32.075,31.575 r0 top value=33R
R81 "Resistor" R0402 39.275,30.325 r270 top value=12K1
R82 "Resistor" R0402 32.075,30.5 r0 top value=33R
R83 "Resistor" R0402 32.075,29.425 r0 top value=33R
R84 "Resistor" R0402 35.1,27.275 r270 top value=49R9
R85 "Resistor" R0402 36.15,27.275 r270 top value=49R9
R86 "Resistor" R0402 37.2,27.275 r270 top value=49R9
R87 "Resistor" R0402 38.25,27.275 r270 top value=49R9
R88 "Resistor" R0402 25.725,20.975 r270 top value=10K
R89 "Resistor" R0402 40.125,20.925 r90 top value=75R
R90 "Resistor" R0402 19.075,20.025 r180 top value=2K4
R91 "Resistor" R0402 19.075,18.95 r180 top value=10K
R92 "Resistor" R0402 38,18.5 r270 top value=75R
R93 "Resistor" R0402 39.05,18.5 r270 top value=75R
R94 "Resistor" R0402 40.125,18.5 r270 top value=75R
R95 "Resistor" R0402 57.325,13.425 r270 top value=270R
R96 "Resistor" R0402 40.748,12.973 r90 top value=10K
R97 "Resistor" R0402 19.05,21.6 r180 top value=0R
R98 "Resistor" R0402 38.725,12.975 r270 top value=10K
R99 "Resistor" R0603 55,103.775 r180 top value=0R
R100 "Resistor" R0402 13.525,11.5 r270 top value=68K
R101 "Resistor" R0402 14.95,11.5 r90 top value=100K
R102 "Resistor" R0402 40.75,11.125 r270 top value=270R
R103 "Resistor" R0603 9.25,11.025 r0 top value=100K
R104 "Resistor" R0603 11.625,11.025 r0 top value=10K
R105 "Resistor" R0402 9.25,2.075 r270 top value=510R
R106 "Resistor" R0603 30.25,50.25 r0 top value=0R
R107 "Resistor" R0603 30.25,42.25 r90 top value=0R
R108 "Resistor" R0603 37.475,42.05 r270 top value=0R
R109 "Resistor" R0603 38.825,42.05 r270 top value=0R
R110 "Resistor" R0402 20.375,102.6 r270 top value=10K
R111 "Resistor" R0603 50.05,89.675 r180 top value=47K
R112 "Resistor" R0402 48.075,90.125 r90 top value=100K
R115 "Resistor" R0402 24.3,23.825 r270 top value=1M3
SB1 "SB_ON" SOLDER-BRIDGE_R0603-0R 28.15,56.78 r270 top locked
SB2 "SB_ON" SOLDER-BRIDGE_R0603-0R 32.125,56.78 r270 top locked
SB3 "SB_ON" SOLDER-BRIDGE_R0603-0R 34.306,55.039 r270 top locked
SB4 "SB_ON" SOLDER-BRIDGE_R0603-0R 39.256,54.914 r270 top locked
SB5 "SB_ON" SOLDER-BRIDGE_R0603-0R 35.681,55.039 r270 top locked
SB6 "SB_ON" SOLDER-BRIDGE_R0603-0R 53.25,67.5 r0 top value=0R
SB7 "SB_ON" SOLDER-BRIDGE_R0603-0R 10.5,51.375 r180 top value=0R
SB8 "SB_ON" SOLDER-BRIDGE_R0603-0R 53.225,89.65 r180 top value=0R
SB9 "SB_ON" SOLDER-BRIDGE_R0603-0R 53.225,91.05 r180 top value=0R
SB10 "SB_ON" SOLDER-BRIDGE_R0402-0R 53.225,86.825 r0 top value=0R
SB11 "SB_ON" SOLDER-BRIDGE_R0603-0R 33,48.75 r180 top value=0R
SB12 "SB_ON" SOLDER-BRIDGE_R0603-0R 33,50.25 r180 top value=0R
SB13 "SB_ON" SOLDER-BRIDGE_R0603-0R 37.75,9.75 r270 top value=0R
SB14 "SB_ON" SOLDER-BRIDGE_R0402-0R 21.5,76 r180 top value=0R
SB15 "SB_ON" SOLDER-BRIDGE_R0603-0R 13.85,49.875 r180 top value=0R
SB16 "SB_ON" SOLDER-BRIDGE_R0603-0R 13.85,48.375 r180 top value=0R
SB17 "SB_ON" SOLDER-BRIDGE_R0603-0R 10.5,46 r180 top value=0R
SB18 "SB_ON" SOLDER-BRIDGE_R0603-0R 10.5,44.5 r180 top value=0R
SB19 "SB_ON" SOLDER-BRIDGE_R0603-0R 45.25,57.625 r180 top value=0R
SB20 "SB_ON" SOLDER-BRIDGE_R0603-0R 10.5,43 r180 top value=0R
SB21 "SB_ON" SOLDER-BRIDGE_R0603-0R 10.5,41.5 r180 top value=0R
SB22 "SB_ON" SOLDER-BRIDGE_R0603-0R 10.5,40 r180 top value=0R
SB23 "SB_ON" SOLDER-BRIDGE_R0603-0R 19.75,35.7 r180 top value=0R
SB24 "SB_ON" SOLDER-BRIDGE_R0603-0R 19.75,33.95 r180 top value=0R
SB25 "SB_ON" SOLDER-BRIDGE_R0603-0R 43.625,46.6 r180 top value=0R
SB26 "SB_ON" SOLDER-BRIDGE_R0603-0R 19.75,30.45 r180 top value=0R
SB27 "SB_ON" SOLDER-BRIDGE_R0603-0R 19.75,28.7 r180 top value=0R
SB28 "SB_ON" SOLDER-BRIDGE_R0603-0R 19.75,32.2 r180 top value=0R
SB29 "SB_ON" SOLDER-BRIDGE_R0603-0R 59.25,52.875 r0 top value=0R
SB30 "SB_ON" SOLDER-BRIDGE_R0603-0R 55.9,49.5 r0 top value=0R
SB31 "SB_ON" SOLDER-BRIDGE_R0603-0R 59.25,51.375 r0 top value=0R
SB32 "SB_ON" SOLDER-BRIDGE_R0603-0R 59.25,42 r0 top value=0R
SB33 "SB_ON" SOLDER-BRIDGE_R0603-0R 59.25,45 r0 top value=0R
SB34 "SB_ON" SOLDER-BRIDGE_R0603-0R 55.9,48 r0 top value=0R
SB35 "SB_ON" SOLDER-BRIDGE_R0603-0R 31.525,32.825 r0 top value=0R
SB36 "SB_ON" SOLDER-BRIDGE_R0603-0R 59.25,46.5 r0 top value=0R
SB37 "SB_ON" SOLDER-BRIDGE_R0603-0R 59.25,43.5 r0 top value=0R
SB38 "SB_ON" SOLDER-BRIDGE_R0603-0R 36.25,16.8 r90 top value=0R
SB39 "SB_ON" SOLDER-BRIDGE_R0603-0R 33,51.75 r180 top value=0R
SB40 "SB_ON" SOLDER-BRIDGE_R0603-0R 25.25,51 r180 top value=0R
SB43 "SB_ON" SOLDER-BRIDGE_R0603-0R 60.95,4.2 r0 top value=0R
SB44 "SB_ON" SOLDER-BRIDGE_R0603-0R 39.925,4.175 r180 top value=0R
SB45 "SB_ON" SOLDER-BRIDGE_R0402-0R 42.125,56.25 r0 top value=0R
SB46 "SB_ON" SOLDER-BRIDGE_R0402-0R 14.675,85.525 r180 top value=0R
T1 "MOSFET_N-CHANNEL" ICC_SOT23-3L_H1P12 9.25,8.175 r180 top value=NDS7002A
TP1 "Test Point" TP_SMD_0-6MM 56.9,129.15 r270 top
TP2 "Test Point" TP_SMD_1MM 21.5,128.525 r0 top
TP3 "Test Point" TP_SMD_0-6MM 24.2,128.025 r270 top
TP4 "Test Point" TP_SMD_0-6MM 25.525,128 r270 top
TP5 "Test Point" TP_SMD_0-6MM 51.65,127.8 r270 top
TP6 "Test Point" TP_SMD_0-6MM 56.9,127.8 r270 top
TP7 "Test Point" TP_SMD_0-6MM 61.875,127.8 r270 top
TP8 "Test Point" TP_SMD_0-6MM 9.45,127.675 r270 top
TP9 "Test Point" TP_SMD_0-6MM 18.15,125.6 r270 top
TP10 "Test Point" TP_SMD_0-6MM 61.875,125.525 r270 top
TP11 "Test Point" TP_SMD_0-6MM 51.775,125.375 r270 top
TP12 "Test Point" TP_SMD_0-6MM 13.675,124.975 r270 top
TP13 "Test Point" TP_SMD_0-6MM 29.1,123.775 r270 top
TP15 "Test Point" TP_SMD_0-6MM 13.675,123.5 r270 top
TP16 "Test Point" TP_SMD_0-6MM 14.4,122.2 r270 top
TP17 "Test Point" TP_SMD_0-6MM 13.025,122.175 r270 top
TP21 "Test Point" TP_SMD_0-6MM 41.1,120.675 r270 top
TP22 "Test Point" TP_SMD_0-6MM 37.7,120.2 r0 top
TP23 "Test Point" TP_SMD_0-6MM 42.65,118.35 r270 top
TP24 "Test Point" TP_SMD_0-6MM 32.475,117.65 r270 top
TP25 "Test Point" TP_SMD_0-6MM 10.7,117.5 r270 top
TP26 "Test Point" TP_SMD_0-6MM 35.4,116.25 r270 top
TP27 "Test Point" TP_SMD_0-6MM 32.35,115.65 r270 top
TP28 "Test Point" TP_SMD_0-6MM 42.4,115.25 r270 top
TP29 "Test Point" TP_SMD_0-6MM 33.75,114.95 r270 top
TP30 "Test Point" TP_SMD_0-6MM 36.625,113.375 r270 top
TP31 "Test Point" TP_SMD_0-6MM 15.35,113.075 r270 top
TP32 "Test Point" TP_SMD_0-6MM 43.2,111.775 r270 top
TP33 "Test Point" TP_SMD_0-6MM 44.575,111.775 r270 top
TP34 "Test Point" TP_SMD_0-6MM 17.05,110.425 r270 top
TP35 "Test Point" TP_SMD_0-6MM 32.775,107.075 r0 top
TP36 "Test Point" TP_SMD_0-6MM 38,107.075 r0 top
TP37 "Test Point" TP_SMD_0-6MM 18.9,106.95 r270 top
TP38 "Test Point" TP_SMD_0-6MM 61.875,106.25 r270 top
TP39 "Test Point" TP_SMD_0-6MM 63.275,106.25 r270 top
TP41 "Test_Point_PTH_1mm_2mm" TP_PTH_1MM_2MM 47.5,99.25 r180 top
TP42 "Test_Point_PTH_1mm_2mm" TP_PTH_1MM_2MM 27,95.5 r0 top
TP43 "Test Point" TP_SMD_0-6MM 40.75,98.75 r180 top
TP45 "Test Point" TP_SMD_0-6MM 17.25,90 r270 top
TP46 "Test Point" TP_SMD_0-6MM 17.25,98.5 r270 top
TP52 "Test Point" TP_SMD_0-6MM 31.875,86.125 r180 top
TP53 "Test Point" TP_SMD_0-6MM 20.25,64.125 r180 top
TP54 "Test Point" TP_SMD_0-6MM 35.555,40.875 r270 top value=N/A
TP55 "Test Point" TP_SMD_0-6MM 39.75,37.175 r270 top value=N/A
TP56 "Test Point" TP_SMD_0-6MM 38.25,30.05 r270 top value=N/A
TP57 "Test Point" TP_SMD_0-6MM 33.925,28.9 r270 top value=N/A
TP65 "Test Point" TP_SMD_0-6MM 56.5,15 r270 top value=N/A
TP67 "Test Point" TP_SMD_0-6MM 39.625,8.875 r0 top value=N/A
TP69 "Test Point" TP_SMD_0-6MM 58.475,12.975 r270 top value=N/A
TP72 "Test Point" TP_SMD_0-6MM 39.625,10.675 r270 top value=N/A
U1 "IC_STM32H5E5ZJT6" ICC_LQFP144_20X20_P050_SOCKET_YAMAICHI_IC149-144-145-B5_NM 35.15,71 r90 top locked value=STM32H5E5ZJT6
U2 "STLINK-V3EC" ICC_UFBGA201_176+25_10X10_P065 22.95,119.425 r90 top
U3 "ECMF2-40A100N6" ESD_UQFN-6L_1P45X1P4_P040 40.05,122.975 r90 top
U4 "ESD-TRANSIL" ESD_QFN1610_2N_1K_2A 45.975,122.875 r0 top value=ESDA25P35-1U1M
U5 "ESD-TRANSIL" ESD_0201_H0P3_1K_2A 8.8,118.95 r90 top value=ESDZL5-1F4
U6 "ESD-TRANSIL" ESD_0201_H0P3_1K_2A 8.8,117.675 r90 top value=ESDZL5-1F4
U7 "LS0505EVD22" ICC_DFN8-EPAD_2X2_P050_H0P8 45.825,116.4 r0 top
U8 "TPS259535DSG" ICC_WSON8-EPAD_2X2_P050 40,116.375 r270 top
U9 "ESD-TRANSIL" ESD_0201_H0P3_1K_2A 10.7,116.375 r90 top value=ESDZL5-1F4
U10 "ESD-TRANSIL" ESD_0201_H0P3_1K_2A 8.8,120.2 r90 top value=ESDZL5-1F4
U11 "ST730M33R" ICC_SOT23-5L_H1P45 33.125,111.125 r90 top
U12 "ESD-TRANSIL" ESD_0201_H0P3_1K_2A 14.975,106.85 r0 top value=ESDZL5-1F4
U13 "ESD-TRANSIL" ESD_0201_H0P3_1K_2A 21.775,102.325 r90 top value=ESDZL5-1F4
U14 "ESD-TRANSIL" ESD_0201_H0P3_1K_2A 37.925,101.975 r270 top value=ESDZL5-1F4
U15 "LD39200PU33R" ICC_DFN6-EPAD_3X3_P095 44,97.75 r90 top
U16 "ST1S40IPUR" ICC_VFQFPN8-EPAD_4X4_P080 22,96.75 r180 top
U17 "LAN8742A-CZ-TR" ICC_VQFN24-EPAD_4X4_P050 36.825,34.175 r180 top
U18 "USBLC6-4SC6" ESD_SOT23-6L 47.25,31.05 r0 top
U19 "KMS-1102NL" TRS_DGKYD_KMS-1102NL 47.325,22.625 r180 top
U20 "ESD-TRANSIL" ESD_0201_H0P3_1K_2A 8.8,121.475 r90 top value=ESDZL5-1F4
U21 "TCPP01-M12" ICC_QFN12L-EPAD_3X3_P050 22.75,20.525 r180 top
U22 "ECMF2-40A100N6" ESD_UQFN-6L_1P45X1P4_P040 19.62,11.635 r0 top locked
U23 "ESD-TRANSIL" ESD_QFN1610_2N_1K_2A 22.67,9.735 r0 top value=ESDA25P35-1U1M
U24 "ESD-TRANSIL" ESD_0201_H0P3_1K_2A 8.8,122.75 r90 top value=ESDZL5-1F4
U25 "ESD-TRANSIL" ESD_0201_H0P3_1K_2A 10.7,115.1 r90 top value=ESDZL5-1F4
U26 "ESD-TRANSIL" ESD_0201_H0P3_1K_2A 10.7,113.825 r90 top value=ESDZL5-1F4
U27 "ESD-TRANSIL" ESD_0201_H0P3_1K_2A 10.7,112.6 r90 top value=ESDZL5-1F4
U28 "ESD-TRANSIL" ESD_0201_H0P3_1K_2A 10.7,111.325 r90 top value=ESDZL5-1F4
X1 "XTAL_4_PINS" CRY_NX2016SA_4P 21.175,112.275 r0 top locked value=24MHz
X2 "XTAL_2_PINS" CRY_NX1610SE_2P 30.125,54.505 r180 top locked value=32.768kHz
X3 "XTAL_4_PINS" CRY_NX1612SA_4P 37.381,52.639 r0 top locked value=48MHz
X4 "XTAL_4_PINS" CRY_NX2016SA_4P 43.225,34.05 r90 top locked value=25MHz

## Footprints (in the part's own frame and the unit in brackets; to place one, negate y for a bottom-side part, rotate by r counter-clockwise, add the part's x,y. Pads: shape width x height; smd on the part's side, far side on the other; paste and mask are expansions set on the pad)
C0402 [mm]
  rect 0.51x0.56 smd mask+0.05: 1(-0.45,0) 2(0.45,0)
  body extent -0.5,-0.3 0.5,0.3, height 0.4
C0402_H0P5 [mm] "MCD-03898"
  rect 0.55x0.5 smd mask+0.05: 1(-0.45,0) 2(0.45,0)
  body extent -0.53,-0.28 0.53,0.27, height 0.55
C0402_MURATA_GRM155_H0P5 [mm] "MCD-03662"
  rect 0.55x0.5 smd mask+0.05: 1(-0.45,0) 2(0.45,0)
  body extent -0.53,-0.28 0.53,0.27, height 0.55
C0603 [mm]
  rect 0.64x0.89 smd mask+0.05: 1(-0.7,0) 2(0.7,0)
  silkscreen extent -0.9,-0.55 1.05,0.55, body extent -0.9,-0.5 0.9,0.5, height 1.4
C0603_H0P8 [mm] "MCD-01540"
  rect 0.64x0.89 smd mask+0.05: 1(-0.7,0) 2(0.7,0)
  silkscreen extent -0.9,-0.55 0.9,0.55, body extent -0.9,-0.5 0.9,0.5, height 1
C0805 [mm]
  rect 0.9x1.4 smd mask+0.05: 1(-0.85,0) 2(0.85,0)
  silkscreen extent -1.3,-0.77 1.3,0.77, body extent -1.1,-0.7 1.1,0.7, height 1.35
C1206_H1P6 [mm]
  rect 1.4x1.78 smd mask+0.05: 1(-1.4,0) 2(1.4,0)
  silkscreen extent -2.12,-0.97 2.15,0.97, body extent -1.7,-0.9 1.7,0.9, height 1.8
CON_AMPHENOL_MDT-420-A-03001 [mm] "MCD-03856"
  round 0 hole 1.15 unplated mask+0.05: 0(-10,-1.5)
  round 0 hole 1.65 unplated mask+0.05: 0(10,-1.5)
  rect 0.3x1.55 smd mask+0.05: 1(-9.25,3.775) 2(-9,-3.775) 3(-8.75,3.775) 4(-8.5,-3.775) 5(-8.25,3.775) 6(-8,-3.775) 7(-7.75,3.775) 16(-5.5,-3.775) 17(-5.25,3.775) 18(-5,-3.775) 19(-4.75,3.775) 20(-4.5,-3.775) 21(-4.25,3.775) 22(-4,-3.775) 23(-3.75,3.775) 24(-3.5,-3.775) 25(-3.25,3.775) 26(-3,-3.775) 27(-2.75,3.775) 28(-2.5,-3.775) 29(-2.25,3.775) 30(-2,-3.775) 31(-1.75,3.775) 32(-1.5,-3.775) 33(-1.25,3.775) 34(-1,-3.775) 35(-0.75,3.775) 36(-0.5,-3.775) 37(-0.25,3.775) 38(0,-3.775) 39(0.25,3.775) 40(0.5,-3.775) 41(0.75,3.775) 42(1,-3.775) 43(1.25,3.775) 44(1.5,-3.775) 45(1.75,3.775) 46(2,-3.775) 47(2.25,3.775) 48(2.5,-3.775) 49(2.75,3.775) 50(3,-3.775) 51(3.25,3.775) 52(3.5,-3.775) 53(3.75,3.775) 54(4,-3.775) 55(4.25,3.775) 56(4.5,-3.775) 57(4.75,3.775) 58(5,-3.775) 59(5.25,3.775) 60(5.5,-3.775) 61(5.75,3.775) 62(6,-3.775) 63(6.25,3.775) 64(6.5,-3.775) 65(6.75,3.775) 66(7,-3.775) 67(7.25,3.775) 68(7.5,-3.775) 69(7.75,3.775) 70(8,-3.775) 71(8.25,3.775) 72(8.5,-3.775) 73(8.75,3.775) 74(9,-3.775) 75(9.25,3.775)
  rect 1.2x2.75 smd mask+0.05: S1(-10.35,3) S2(10.35,3)
  silkscreen extent -10.95,-3.77 10.95,1.24, body extent -11,-4.33 11,4.23, height 4.2
CON_RJ45_DGKYD_KRJ-CB4.2GYZNL [mm] "RJ45  connector, right angle"
  rect 1x1 hole 0.7 mask+0.05: 1(3.57,10.6)
  round 1 hole 0.7 mask+0.05: 2(2.55,11.7) 3(1.53,10.6) 4(0.51,11.7) 5(-0.51,10.6) 6(-1.53,11.7) 7(-2.55,10.6) 8(-3.57,11.7) 9(7.06,9.52) 10(4.77,9.52) 11(-4.77,9.52) 12(-7.06,9.52)
  oval 1.3x2.8 hole 0.7 slot 2.2 at 90 deg mask+0.05: SH1(8.04,4.2) SH2(-8.04,4.2)
  Multi-Layer keep-out lines w0.1: -9,0 -7,0 -7,6.4 cw(c-7,7.3) -7,8.2 7,8.2 cw(c7,7.3) 7,6.4 7,0 9,0
  silkscreen extent -8.23,-4.1 8.22,11.45, body extent -8.39,-4.1 8.39,11.9, height 6.85
CON_SAMTEC_FTSH-110-01-L-DV [mm]
  rect 0.74x2.79 smd mask+0.05: 1(-5.715,-2.035) 2(-5.715,2.035) 3(-4.445,-2.035) 4(-4.445,2.035) 5(-3.175,-2.035) 6(-3.175,2.035) 7(-1.905,-2.035) 8(-1.905,2.035) 9(-0.635,-2.035) 10(-0.635,2.035) 11(0.635,-2.035) 12(0.635,2.035) 13(1.905,-2.035) 14(1.905,2.035) 15(3.175,-2.035) 16(3.175,2.035) 17(4.445,-2.035) 18(4.445,2.035) 19(5.715,-2.035) 20(5.715,2.035)
  silkscreen extent -6.35,-1.71 6.35,1.71, body extent -6.35,-2.92 6.35,2.92, height 5.97
CON_SAMTEC_SSW-106-01-X-S [mm] "MCD-02079"
  rect 1.85x1.85 / inner round 1.85 / far side rect 1.85x1.85 hole 1.1 mask+0.05: 1(-6.35,0)
  round 1.85 hole 1.1 mask+0.05: 2(-3.81,0) 3(-1.27,0) 4(1.27,0) 5(3.81,0) 6(6.35,0)
  silkscreen extent -7.88,-1.2 7.88,1.2, body extent -7.88,-1.21 7.88,1.21, height 8.51
CON_SAMTEC_SSW-108-01-X-S [mm] "MCD-01743"
  rect 1.85x1.85 / inner round 1.85 / far side rect 1.85x1.85 hole 1.1 mask+0.05: 1(-8.89,0)
  round 1.85 hole 1.1 mask+0.05: 2(-6.35,0) 3(-3.81,0) 4(-1.27,0) 5(1.27,0) 6(3.81,0) 7(6.35,0) 8(8.89,0)
  silkscreen extent -10.42,-1.2 10.42,1.2, body extent -10.42,-1.21 10.42,1.21, height 8.51
CON_SAMTEC_SSW-110-01-X-S [mm] "MCD-02080"
  rect 1.85x1.85 / inner round 1.85 / far side rect 1.85x1.85 hole 1.1 mask+0.05: 1(-11.43,0)
  round 1.85 hole 1.1 mask+0.05: 2(-8.89,0) 3(-6.35,0) 4(-3.81,0) 5(-1.27,0) 6(1.27,0) 7(3.81,0) 8(6.35,0) 9(8.89,0) 10(11.43,0)
  silkscreen extent -12.96,-1.2 12.96,1.2, body extent -12.96,-1.21 12.96,1.21, height 8.51
CON_SAMTEC_TSW-102-07-G-S [mm]
  rect 1.85x1.85 / inner round 1.85 / far side rect 1.85x1.85 hole 1 mask+0.05: 1(-1.27,0)
  round 1.85 hole 1 mask+0.05: 2(1.27,0)
  silkscreen extent -2.58,-1.3 2.58,1.3, body extent -2.67,-1.3 2.58,1.3, height 8.38
CON_SAMTEC_TSW-102-09-X-S [mm]
  rect 1.85x1.85 / inner round 1.85 / far side rect 1.85x1.85 hole 1 mask+0.05: 1(-1.27,0)
  round 1.85 hole 1 mask+0.05: 2(1.27,0)
  silkscreen extent -2.64,-1.37 2.64,1.37, body extent -2.67,-1.3 2.58,1.3, height 8.38
CON_SAMTEC_TSW-104-07-G-S [mm]
  rect 1.85x1.85 / inner round 1.85 / far side rect 1.85x1.85 hole 1 mask+0.05: 1(-3.81,0)
  round 1.85 hole 1 mask+0.05: 2(-1.27,0) 3(1.27,0) 4(3.81,0)
  silkscreen extent -5.12,-1.3 5.12,1.3, body extent -5.21,-1.37 5.18,1.37, height 8.38
CON_SAMTEC_TSW-104-07-X-D [mm]
  rect 1.85x1.85 / inner round 1.85 / far side rect 1.85x1.85 hole 1 mask+0.05: 1(-3.81,-1.27)
  round 1.85 hole 1 mask+0.05: 2(-3.81,1.27) 3(-1.27,-1.27) 4(-1.27,1.27) 5(1.27,-1.27) 6(1.27,1.27) 7(3.81,-1.27) 8(3.81,1.27)
  silkscreen extent -5.08,-2.54 5.08,2.54, body extent -5.08,-2.54 5.08,2.54, height 8.38
CON_SAMTEC_TSW-116-07-G-D [mm] "MCD-02536"
  rect 1.85x1.85 / inner round 1.85 / far side rect 1.85x1.85 hole 1 mask+0.05: 1(-19.05,-1.27)
  round 1.85 hole 1 mask+0.05: 2(-19.05,1.27) 3(-16.51,-1.27) 4(-16.51,1.27) 5(-13.97,-1.27) 6(-13.97,1.27) 7(-11.43,-1.27) 8(-11.43,1.27) 9(-8.89,-1.27) 10(-8.89,1.27) 11(-6.35,-1.27) 12(-6.35,1.27) 13(-3.81,-1.27) 14(-3.81,1.27) 15(-1.27,-1.27) 16(-1.27,1.27) 17(1.27,-1.27) 18(1.27,1.27) 19(3.81,-1.27) 20(3.81,1.27) 21(6.35,-1.27) 22(6.35,1.27) 23(8.89,-1.27) 24(8.89,1.27) 25(11.43,-1.27) 26(11.43,1.27) 27(13.97,-1.27) 28(13.97,1.27) 29(16.51,-1.27) 30(16.51,1.27) 31(19.05,-1.27) 32(19.05,1.27)
  silkscreen extent -20.32,-2.54 20.32,2.54, body extent -20.32,-2.55 20.32,2.54, height 8.38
